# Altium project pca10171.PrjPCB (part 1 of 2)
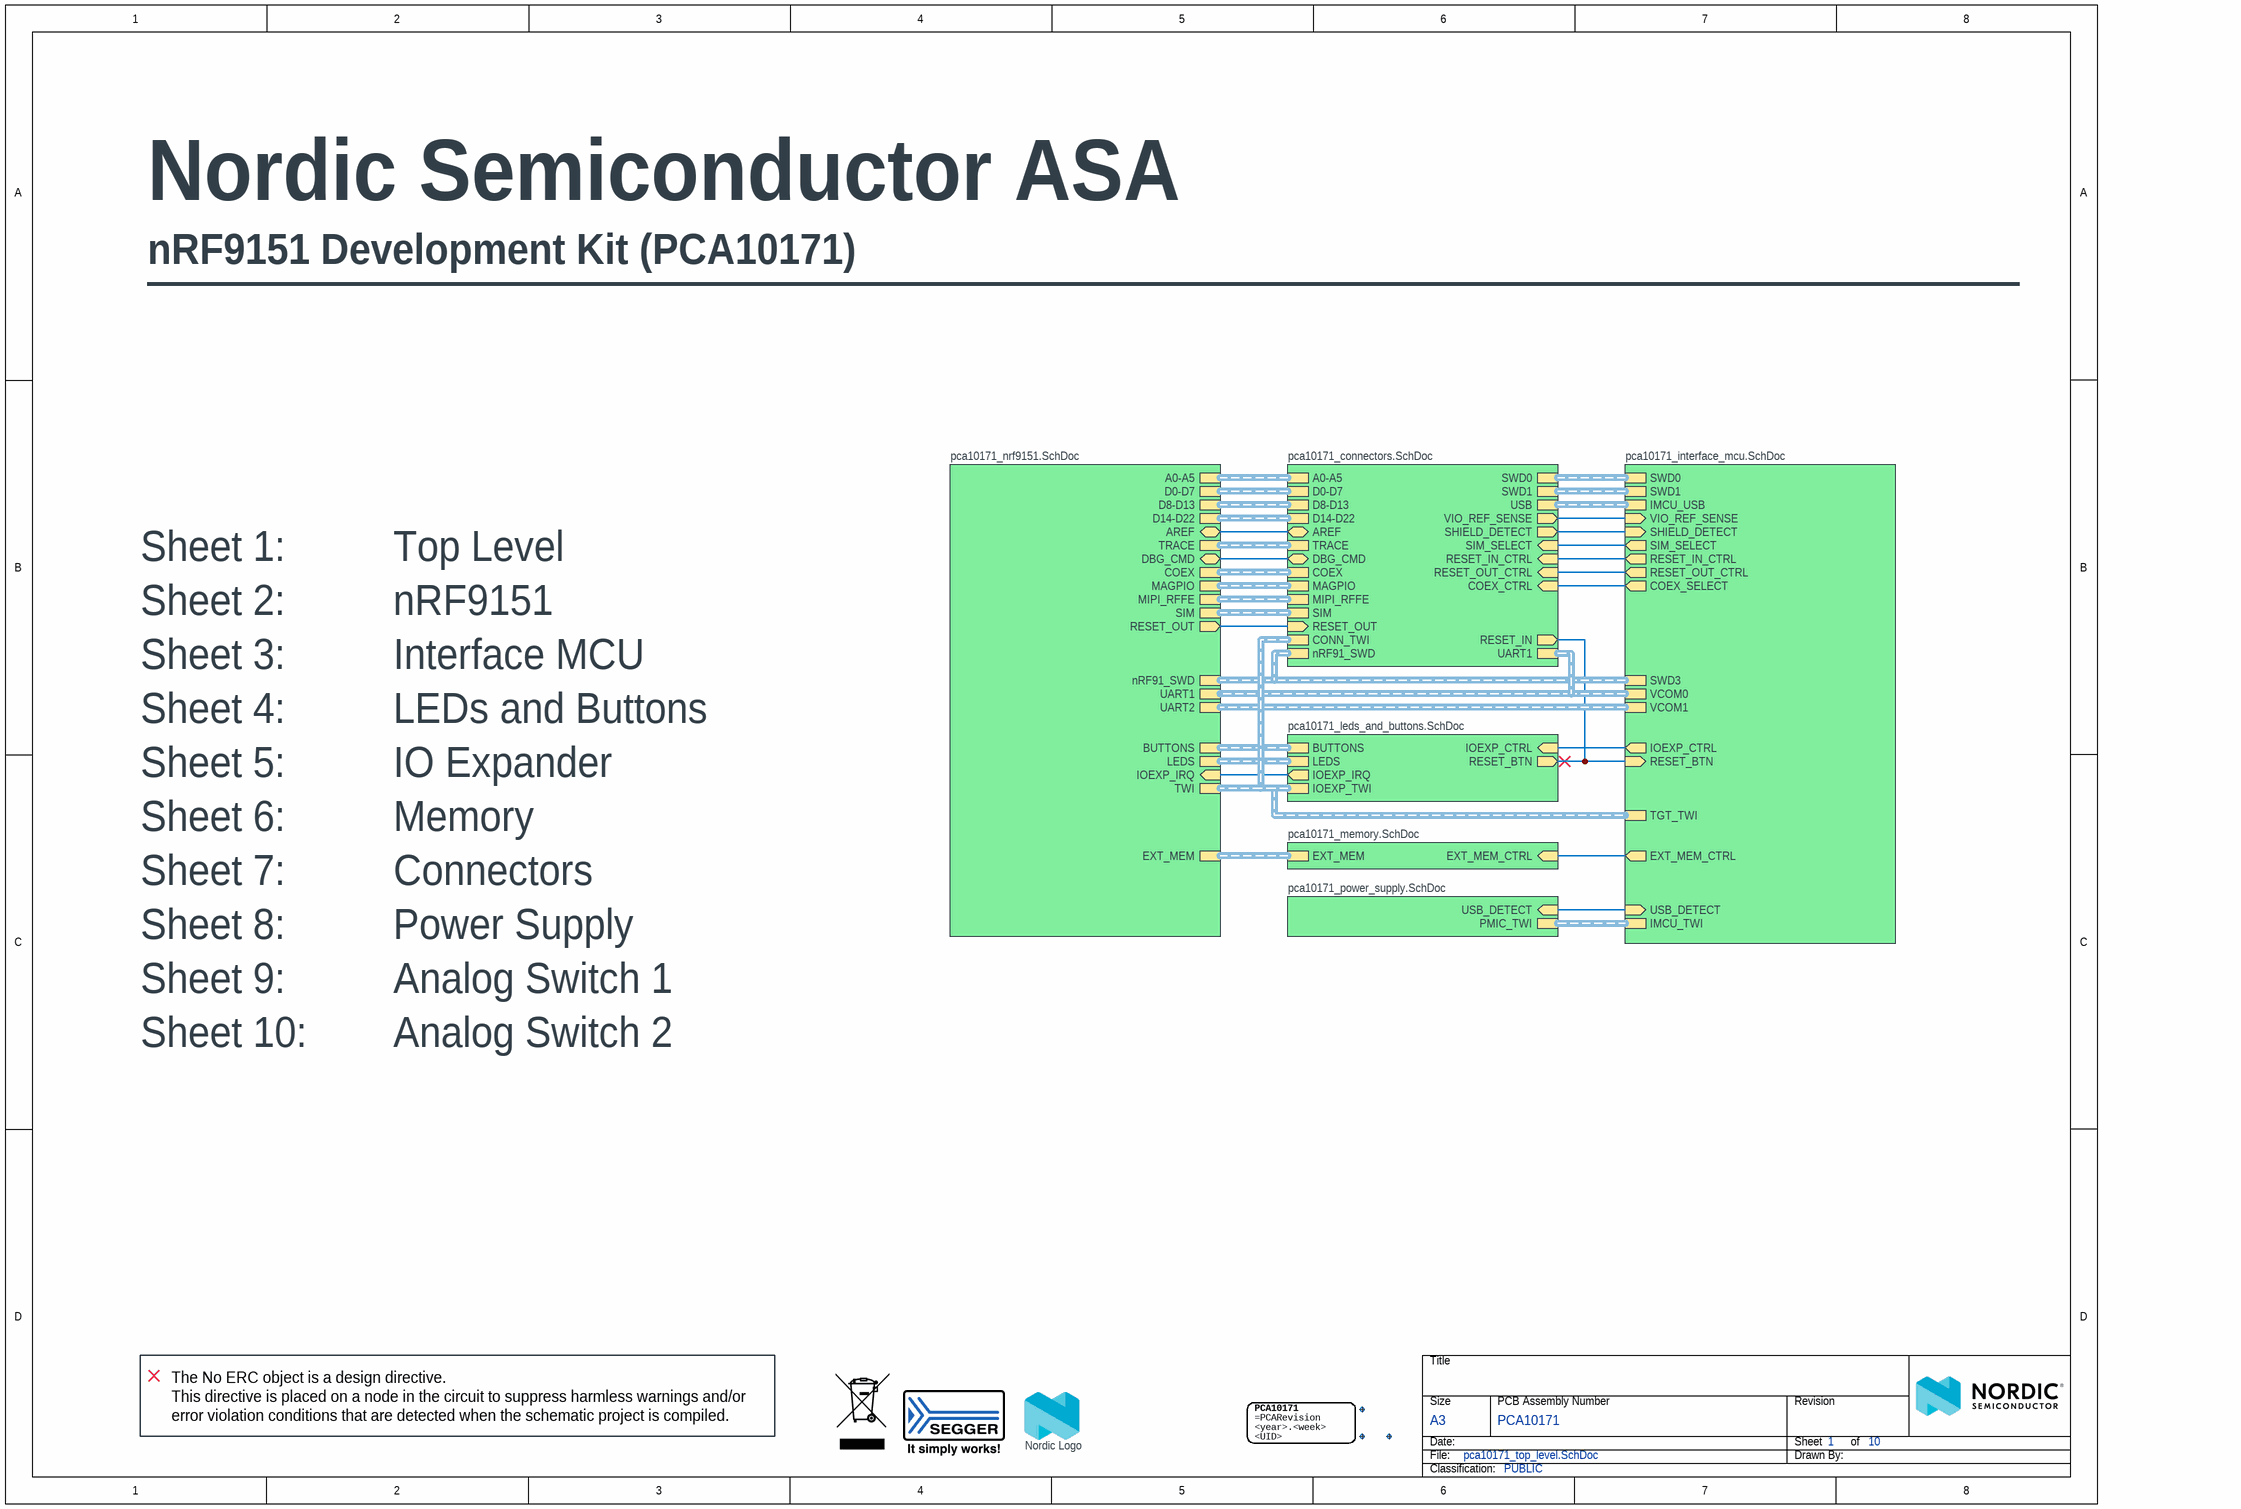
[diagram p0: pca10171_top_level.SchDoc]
BoardThickness: 1.6mm; BoardTitle: nRF9151 Development Kit; Classification: PUBLIC; Compliance: RoHS, REACH, Halogen-Free; Designer: KOD1; Dielectric: FR-4; NrOfLayers: 4; Organization: Nordic Semiconductor; PCAName: PCA10171; PCARevision: 1.0.0; PCBNumber: 400797; PCBRevision: 0022KOD1; PCBStackup: 4001; ProductName: nRF9151-DK; ProjectName: nRF91 DK; ProjectNumber: 4536; SilkscreenColor: White; SoldermaskColor: Blue; SurfaceFinish: ENIG Gold
10 sheets, 317 parts. Net scope: hierarchical (ports join the sheet entries above them; power ports are global).
Board file: 400797.PcbDoc
Sheets:
  pca10171_top_level.SchDoc
     = pca10171_nrf9151.SchDoc
     = pca10171_interface_mcu.SchDoc
      S1 = pca10171_switch_fsa.SchDoc
      S2 = pca10171_switch_fsa.SchDoc
      S3 = pca10171_switch_fsa.SchDoc
      S4 = pca10171_switch_fsa.SchDoc
     = pca10171_leds_and_buttons.SchDoc
      S5 = pca10171_switch_fsa.SchDoc
      S6 = pca10171_switch_fsa.SchDoc
      S7 = pca10171_switch_nx.SchDoc
      Designator = pca10171_io_expander.SchDoc
     = pca10171_memory.SchDoc
      S8 = pca10171_switch_fsa.SchDoc
     = pca10171_connectors.SchDoc
      S9 = pca10171_switch_nx.SchDoc
      S10 = pca10171_switch_fsa.SchDoc
      S11 = pca10171_switch_fsa.SchDoc
     = pca10171_power_supply.SchDoc

## Sheet pca10171_top_level.SchDoc: =BoardTitle + ' - Top Level'
size A3; Organization: Nordic Semiconductor; DocumentNumber: 1; Revision: 1.0.0; SheetNumber: 1; SheetTotal: 10; Author: KOD1; CompanyName: Nordic Semiconductor; DrawnBy: KOD1; DocumentSize: A3

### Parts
Fid1  Fiducial mark  [Fiducial]  (value not drawn)  (no BOM)
Fid2  Fiducial mark  [Fiducial]  (value not drawn)  (no BOM)
Fid3  Fiducial mark  [Fiducial]  (value not drawn)  (no BOM)
LABEL1  15x40mm  [LabelSilk_15x40]  (value not drawn)
LOGO1  WEE Symbol  [WEE_3x4.5mm]  (value not drawn)  (no BOM)
LOGO2  Segger Logo S  [SEGGER_LOGO_S]  (value not drawn)  (no BOM)
LOGO3  Nordic Logo  [NORDIC_LOGO_LYING]  (no BOM)

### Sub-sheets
? = pca10171_nrf9151.SchDoc: nRF91_SWD (harness SWD), DBG_CMD (bidir), UART1 (harness UART), COEX (harness COEX), UART2 (harness UART), SIM (harness SIM), TWI (harness TWI), A0-A5 (harness 6CH), AREF (bidir), TRACE (harness TRACE), BUTTONS (harness 4CH), LEDS (harness 4CH), IOEXP_IRQ (in), EXT_MEM (harness SPI), MIPI_RFFE (harness MIPI_RFFE), MAGPIO (harness MAGPIO), RESET_OUT (out), D8-D13 (harness 6CH), D14-D22 (harness 9CH), D0-D7 (harness 8CH)
? = pca10171_interface_mcu.SchDoc: VCOM1 (harness UART), VCOM0 (harness UART), USB_DETECT (in), RESET_BTN (in), SWD3 (harness SWD), SWD1 (harness SWD), IMCU_USB (harness USB), SWD0 (harness SWD), COEX_SELECT (out), IOEXP_CTRL (out), SIM_SELECT (out), TGT_TWI (harness TWI), VIO_REF_SENSE (in), IMCU_TWI (harness TWI), RESET_IN_CTRL (out), EXT_MEM_CTRL (out), SHIELD_DETECT (in), RESET_OUT_CTRL (out)
? = pca10171_leds_and_buttons.SchDoc: BUTTONS (harness 4CH), LEDS (harness 4CH), IOEXP_CTRL (in), IOEXP_IRQ (out), RESET_BTN (out), IOEXP_TWI (harness TWI)
? = pca10171_memory.SchDoc: EXT_MEM_CTRL (in), EXT_MEM (harness SPI)
? = pca10171_connectors.SchDoc: COEX (harness COEX), nRF91_SWD (harness SWD), DBG_CMD (bidir), MIPI_RFFE (harness MIPI_RFFE), A0-A5 (harness 6CH), TRACE (harness TRACE), USB (harness USB), SIM (harness SIM), AREF (bidir), MAGPIO (harness MAGPIO), SWD0 (harness SWD), SWD1 (harness SWD), SHIELD_DETECT (out), UART1 (harness UART), SIM_SELECT (in), VIO_REF_SENSE (out), CONN_TWI (harness TWI), RESET_IN_CTRL (in), RESET_OUT (in), RESET_OUT_CTRL (in), RESET_IN (out), D8-D13 (harness 6CH), D14-D22 (harness 9CH), D0-D7 (harness 8CH), COEX_CTRL (in)
? = pca10171_power_supply.SchDoc: USB_DETECT (in), PMIC_TWI (harness TWI)

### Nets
COEX_SELECT: sheet /COEX_SELECT, sheet /COEX_CTRL
DBG_CMD: sheet /DBG_CMD, sheet /DBG_CMD
EXT_MEM_CTRL: sheet /EXT_MEM_CTRL, sheet /EXT_MEM_CTRL
IOEXP_CTRL: sheet /IOEXP_CTRL, sheet /IOEXP_CTRL
P0.19/AIN6: sheet /IOEXP_IRQ, sheet /IOEXP_IRQ
P0.20/AIN7: sheet /AREF, sheet /AREF
P0.21: sheet /RESET_OUT, sheet /RESET_OUT
RESET_BUTTON: sheet /RESET_BTN, sheet /RESET_BTN, sheet /RESET_IN
RESET_IN_CTRL: sheet /RESET_IN_CTRL, sheet /RESET_IN_CTRL
RESET_OUT_CTRL: sheet /RESET_OUT_CTRL, sheet /RESET_OUT_CTRL
SHIELD_DETECT: sheet /SHIELD_DETECT, sheet /SHIELD_DETECT
SIM_SELECT: sheet /SIM_SELECT, sheet /SIM_SELECT
USB_DETECT: sheet /USB_DETECT, sheet /USB_DETECT
VIO_REF_SENSE: sheet /VIO_REF_SENSE, sheet /VIO_REF_SENSE

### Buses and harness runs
harness sheet /CONN_TWI = sheet /IOEXP_TWI = sheet /TGT_TWI = sheet /TWI
harness sheet /IMCU_TWI = sheet /PMIC_TWI
harness sheet /IMCU_USB = sheet /USB
harness sheet /nRF91_SWD = sheet /SWD3
harness sheet /UART1 = sheet /VCOM0
harness sheet /UART2 = sheet /VCOM1

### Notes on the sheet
- Nordic Semiconductor ASA
- ________________________________________________________________
- Sheet 1:          Top Level
- Sheet 2:          nRF9151
- Sheet 3:          Interface MCU
- Sheet 4:          LEDs and Buttons
- Sheet 5:          IO Expander
- Sheet 6:          Memory
- Sheet 7:          Connectors
- Sheet 8:          Power Supply
- Sheet 9:          Analog Switch 1
- Sheet 10:        Analog Switch 2
- The No ERC object is a design directive.
  This directive is placed on a node in the circuit to suppress harmless warnings and/or error violation conditions that are detected when the schematic project is compiled.

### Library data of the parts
Fid1-Fid3 = Fid-Mark: Manufacturer: N.A.; Part number NEMS: 100500073; Value: N.A.; Assembly: Not mounted; Pad Count: 1; Component Status: Active; System: Connector
LABEL1 = Label_15x40: PCA version label, stick-on, 15x40mm; Manufacturer: Ellco Etikett; Manufacturer Part Number: 51945; Part number NEMS: 101200030; Component Status: Active; Pad Count: 0; Note: N.A.; Assembly: See section for "Marking/ Stick-on label specification
LOGO1 = WEEE Symbol 3x4.5mm: WEEE Directive symbol; Manufacturer: N.A.; Part number NEMS: 101100006; Component Status: Active; Pad Count: 0
LOGO2 = Segger Logo S: Segger logo, small size; Manufacturer: N.A.; Part number NEMS: 101100004; Component Status: Active; Pad Count: 0
LOGO3 = Nordic Logo lying: Manufacturer: N.A.; Part number NEMS: 101100001; Component Status: Active; Pad Count: 0

## Sheet pca10171_nrf9151.SchDoc: =BoardTitle + ' - nRF9151'
size A3; Organization: Nordic Semiconductor; DocumentNumber: 2; Revision: 1.0.0; SheetNumber: 2; SheetTotal: 10; Author: KOD1; CompanyName: Nordic Semiconductor; DrawnBy: KOD1; DocumentSize: A3
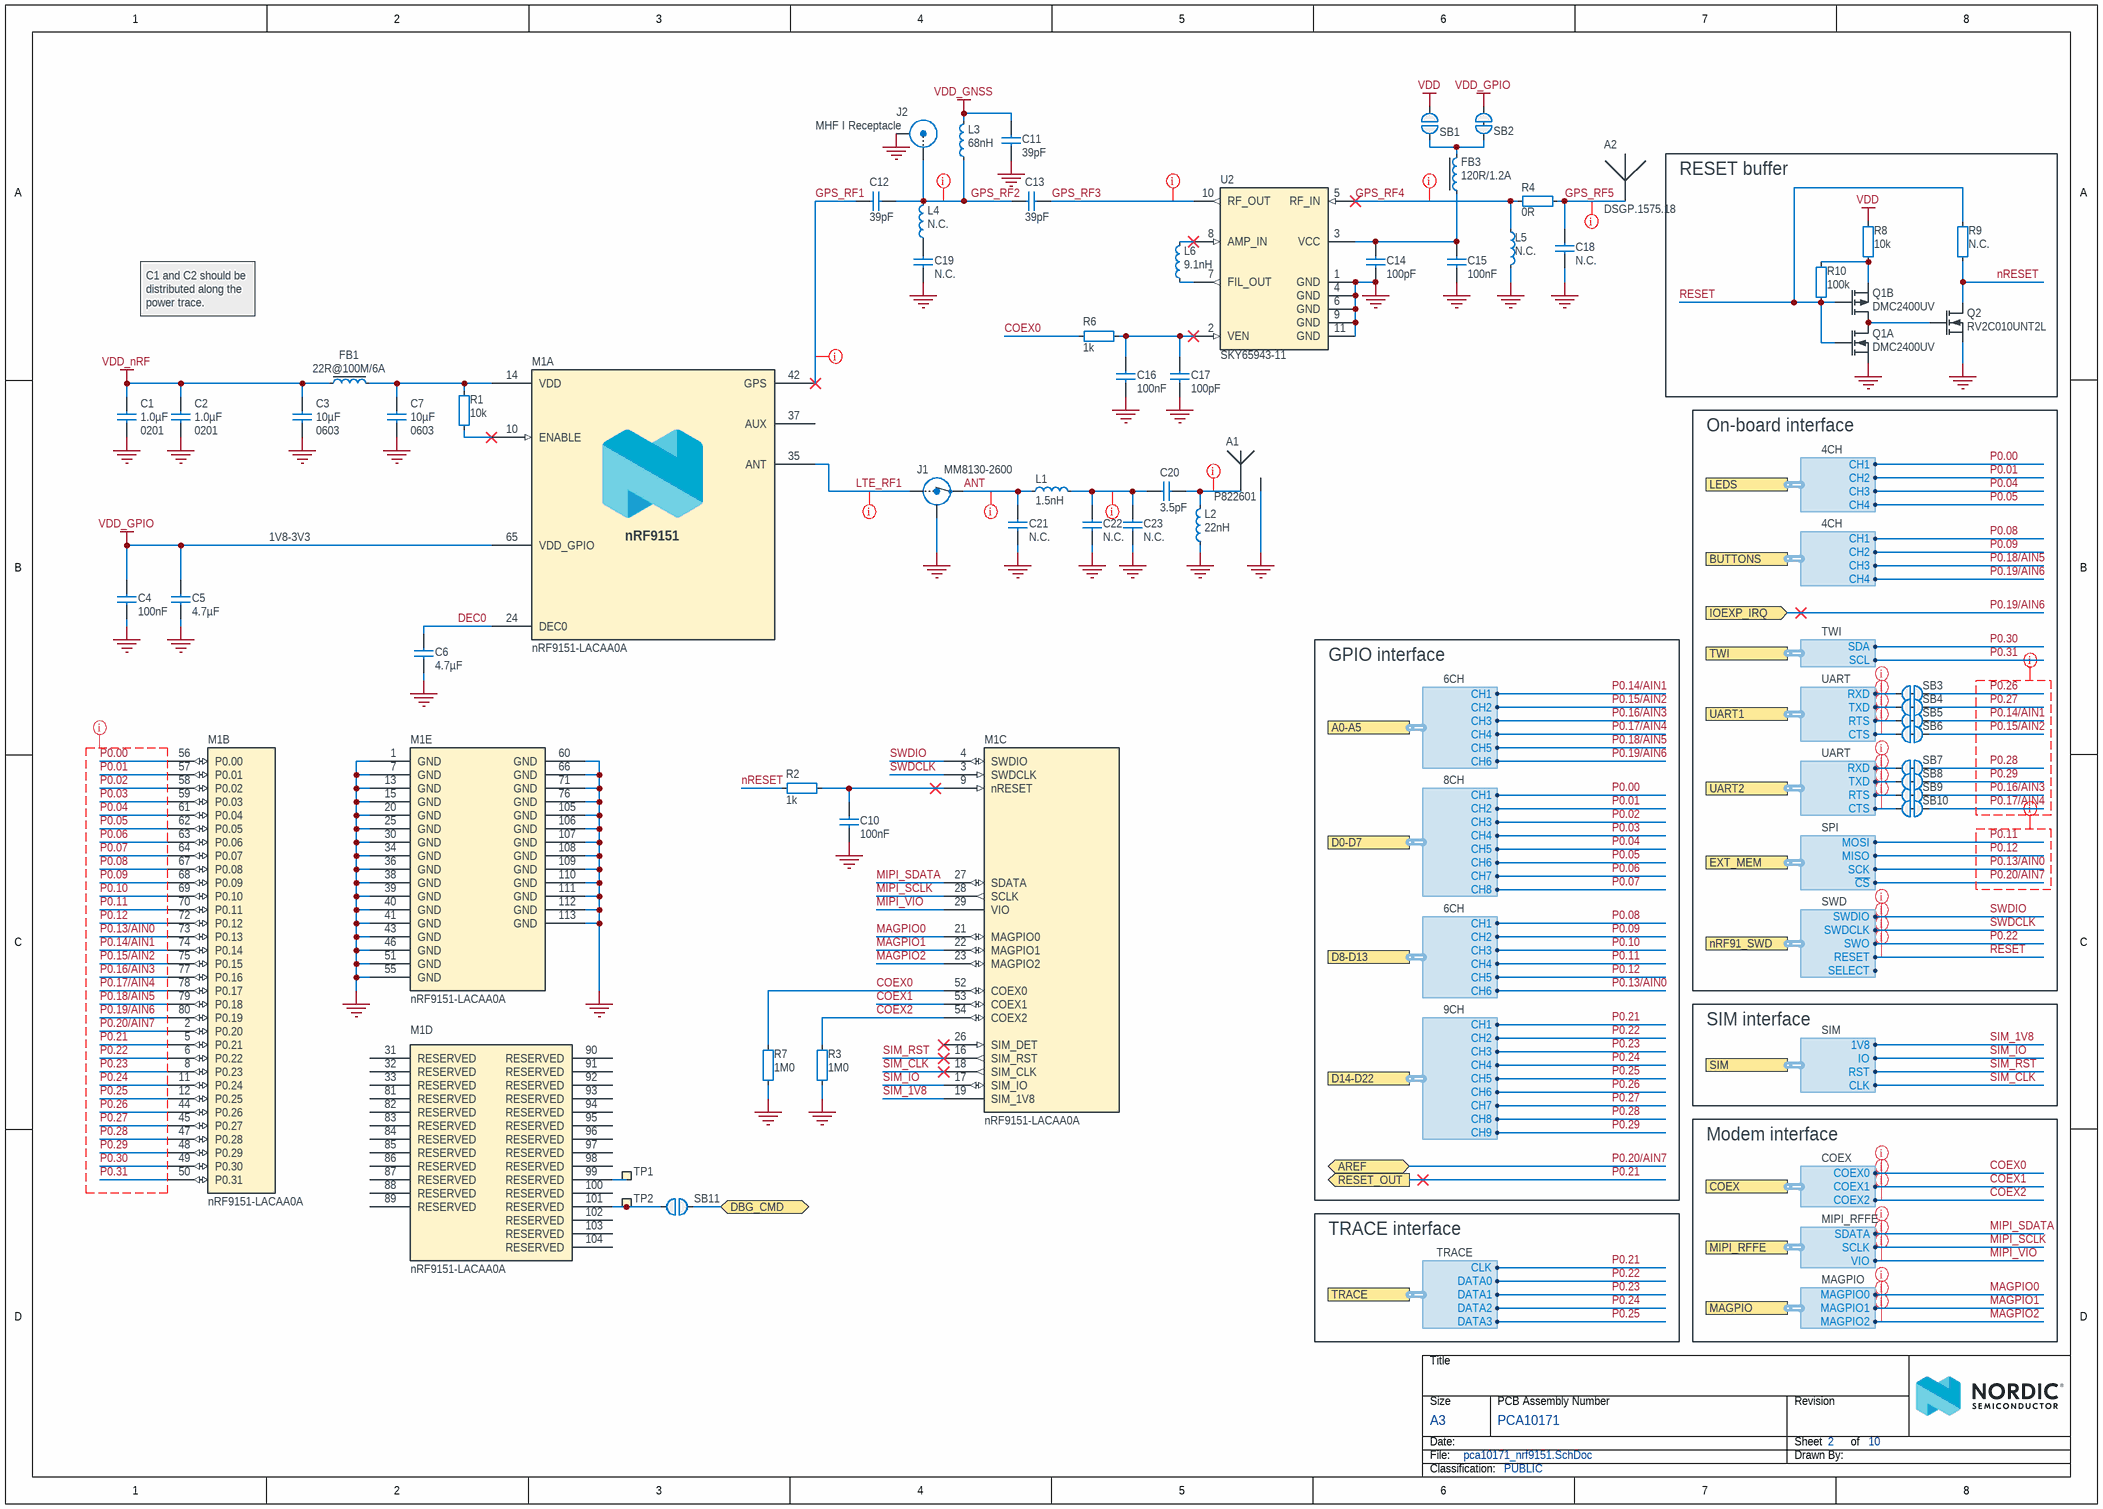
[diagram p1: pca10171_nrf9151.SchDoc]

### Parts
A1  P822601  [P822601]
A2  DSGP.1575.18  [DSGP.1575.18.4.C.02]
C1  1.0µF  Footprint Doc: 0201  [CAPC0603X03L_C]
C2  1.0µF  Footprint Doc: 0201  [CAPC0603X03L_C]
C3  10µF  Footprint Doc: 0603  [CAPC1608X06L]
C4  100nF  [CAPC0603X03L_C]
C5  4.7µF  [CAPC1005X04L]
C6  4.7µF  [CAPC1005X04L]
C7  10µF  Footprint Doc: 0603  [CAPC1608X06L]
C10  100nF  [CAPC0603X03L_C]
C11  39pF  [CAPC0603X03L_C]
C12  39pF  [CAPC0603X03L_C]
C13  39pF  [CAPC0603X03L_C]
C14  100pF  [CAPC0603X03L_C]
C15  100nF  [CAPC0603X03L_C]
C16  100nF  [CAPC0603X03L_C]
C17  100pF  [CAPC0603X03L_C]
C18  N.C.  [CAPC1005X04L_NC]
C19  N.C.  [CAPC0603X03L_C_NC]
C20  3.5pF  [CAPC0603X03L_C]
C21  N.C.  [CAPC0603X03L_C_NC]
C22  N.C.  [CAPC0603X03L_C_NC]
C23  N.C.  [CAPC0603X03L_C_NC]
FB1  22R@100M/6A  [INDC1608X06L]
FB3  120R/1.2A  [INDC1005X04L]
J1  MM8130-2600  [COAXIAL-SWF]
J2  MHF I Receptacle  [COAXIAL RF U.FL-R-SMT-1]
L1  1.5nH  [INDC0603X03L_C]
L2  22nH  [INDC0603X03L_C]
L3  68nH  [INDC1005X04L_WW]
L4  N.C.  [INDC1005X04L_NC]
L5  N.C.  [INDC1005X04L_NC]
L6  9.1nH  [INDC1005X04L_WW]
M1  nRF9151-LACAA0A  [LGA50P1210X1110X130-113N]  (parts A,B,C,D,E of 5)
Q1  DMC2400UV  [SOTFL50P162X60-6N]  (parts A,B of 2)
Q2  RV2C010UNT2L  [DFN65P100X40-3L]
R1  10k  [RESC0603X03L_C]
R2  1k  [RESC0603X03L_C]
R3  1M0  [RESC0603X03L_C]
R4  0R  [RESC1005X04L]
R6  1k  [RESC0603X03L_C]
R7  1M0  [RESC0603X03L_C]
R8  10k  [RESC0603X03L_C]
R9  N.C.  [RESC0603X03L_C_NC]
R10  100k  [RESC0603X03L_C]
SB1  Solderbridge  [Solderbridge]  (value not drawn)  (no BOM)
SB2  Solderbridge  [Solderbridge_Shorted]  (value not drawn)  (net tie, no BOM)
SB3  Solderbridge  [Solderbridge_Shorted]  (value not drawn)  (net tie, no BOM)
SB4  Solderbridge  [Solderbridge_Shorted]  (value not drawn)  (net tie, no BOM)
SB5  Solderbridge  [Solderbridge_Shorted]  (value not drawn)  (net tie, no BOM)
SB6  Solderbridge  [Solderbridge_Shorted]  (value not drawn)  (net tie, no BOM)
SB7  Solderbridge  [Solderbridge_Shorted]  (value not drawn)  (net tie, no BOM)
SB8  Solderbridge  [Solderbridge_Shorted]  (value not drawn)  (net tie, no BOM)
SB9  Solderbridge  [Solderbridge_Shorted]  (value not drawn)  (net tie, no BOM)
SB10  Solderbridge  [Solderbridge_Shorted]  (value not drawn)  (net tie, no BOM)
SB11  Solderbridge  [Solderbridge]  (value not drawn)  (no BOM)
TP1  Ø1.0mm,SMD  [TP_SMD_D1.0mm]  (value not drawn)  (no BOM)
TP2  Ø1.0mm,SMD  [TP_SMD_D1.0mm]  (value not drawn)  (no BOM)
U2  SKY65943-11  [SKY65943-11]

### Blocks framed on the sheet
RESET buffer: Q1 Q2 R8-R10
On-board interface: SB3-SB10

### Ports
A0-A5 (harness 6CH), AREF (bidir), BUTTONS (harness 4CH), COEX (harness COEX), D0-D7 (harness 8CH), D8-D13 (harness 6CH), D14-D22 (harness 9CH), DBG_CMD (bidir), EXT_MEM (harness SPI), IOEXP_IRQ (in), LEDS (harness 4CH), MAGPIO (harness MAGPIO), MIPI_RFFE (harness MIPI_RFFE), nRF91_SWD (harness SWD), RESET_OUT (out), SIM (harness SIM), TRACE (harness TRACE), TWI (harness TWI), UART1 (harness UART), UART2 (harness UART)

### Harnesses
COEX: COEX0, COEX2, COEX1
UART: RTS, CTS, RXD, TXD
SIM: CLK, IO, 1V8, RST
SWD: SWDIO, SWDCLK, SWO, RESET, SELECT
TWI: SCL, SDA
TRACE: CLK, DATA0, DATA1, DATA3, DATA2
SPI: SCK, ~{CS}, MOSI, MISO
MIPI_RFFE: SDATA, VIO, SCLK
MAGPIO: MAGPIO0, MAGPIO2, MAGPIO1
4CH: CH1, CH2, CH3, CH4
6CH: CH1, CH2, CH3, CH4, CH5, CH6
8CH: CH1, CH2, CH3, CH4, CH5, CH6, CH7, CH8
9CH: CH1, CH2, CH3, CH4, CH5, CH6, CH7, CH8, CH9

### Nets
GND: A1.2 A2.2(GND) C1.2 C2.2 C3.2 C4.2 C5.2 C6.2 C7.2 C10.2 C11.1 C14.1 C15.1 C16.1 C17.1 C18.2 C19.1 C21.1 C22.1 C23.1 J1.2(Shield) J2.2(Y) L2.1 L5.2 M1.1(GND) M1.7(GND) M1.13(GND) M1.15(GND) M1.20(GND) M1.25(GND) M1.30(GND) M1.34(GND) M1.36(GND) M1.38(GND) M1.39(GND) M1.40(GND) M1.41(GND) M1.43(GND) M1.46(GND) M1.51(GND) M1.55(GND) M1.60(GND) M1.66(GND) M1.71(GND) M1.76(GND) M1.105(GND) M1.106(GND) M1.107(GND) M1.108(GND) M1.109(GND) M1.110(GND) M1.111(GND) M1.112(GND) M1.113(GND) Q1.1(S1) Q2.2(S) R3.1 R7.1 U2.1(GND) U2.4(GND) U2.6(GND) U2.9(GND) U2.11(GND)
VDD: R8.1 SB1.1
VDD_GNSS: C11.2 L3.1
VDD_GPIO: C4.1 C5.1 M1.65(VDD_GPIO) SB2.1
VDD_nRF: C1.1 C2.1 C3.1 FB1.1
ANT: C21.2 J1.3(OUT) L1.1
COEX0: M1.52(COEX0) R6.1 R7.2 ; port COEX.COEX0
COEX1: M1.53(COEX1) ; port COEX.COEX1
COEX2: M1.54(COEX2) R3.2 ; port COEX.COEX2
DBG_CMD: SB11.1 ; port DBG_CMD
DEC0: C6.1 M1.24(DEC0)
GPS_RF1: C12.2 M1.42(GPS)
GPS_RF2: C12.1 C13.2 J2.1(X) L3.2 L4.1
GPS_RF3: C13.1 U2.10(RF_OUT)
GPS_RF4: L5.1 R4.1 U2.5(RF_IN)
GPS_RF5: A2.1 C18.1 R4.2
LTE_RF1: J1.1(IN) M1.35(ANT)
MAGPIO0: M1.21(MAGPIO0) ; port MAGPIO.MAGPIO0
MAGPIO1: M1.22(MAGPIO1) ; port MAGPIO.MAGPIO1
MAGPIO2: M1.23(MAGPIO2) ; port MAGPIO.MAGPIO2
MIPI_SCLK: M1.28(SCLK) ; port MIPI_RFFE.SCLK
MIPI_SDATA: M1.27(SDATA) ; port MIPI_RFFE.SDATA
MIPI_VIO: M1.29(VIO) ; port MIPI_RFFE.VIO
nRESET: Q2.3(D) R2.1 R9.2
P0.00: M1.56(P0.00) ; port LEDS.CH1, port D0-D7.CH1
P0.01: M1.57(P0.01) ; port LEDS.CH2, port D0-D7.CH2
P0.02: M1.58(P0.02) ; port D0-D7.CH3
P0.03: M1.59(P0.03) ; port D0-D7.CH4
P0.04: M1.61(P0.04) ; port LEDS.CH3, port D0-D7.CH5
P0.05: M1.62(P0.05) ; port LEDS.CH4, port D0-D7.CH6
P0.06: M1.63(P0.06) ; port D0-D7.CH7
P0.07: M1.64(P0.07) ; port D0-D7.CH8
P0.08: M1.67(P0.08) ; port BUTTONS.CH1, port D8-D13.CH1
P0.09: M1.68(P0.09) ; port BUTTONS.CH2, port D8-D13.CH2
P0.10: M1.69(P0.10) ; port D8-D13.CH3
P0.11: M1.70(P0.11) ; port EXT_MEM.MOSI, port D8-D13.CH4
P0.12: M1.72(P0.12) ; port EXT_MEM.MISO, port D8-D13.CH5
P0.13/AIN0: M1.73(P0.13) ; port EXT_MEM.SCK, port D8-D13.CH6
P0.14/AIN1: M1.74(P0.14) SB5.1 ; port A0-A5.CH1
P0.15/AIN2: M1.75(P0.15) SB6.1 ; port A0-A5.CH2
P0.16/AIN3: M1.77(P0.16) SB9.1 ; port A0-A5.CH3
P0.17/AIN4: M1.78(P0.17) SB10.1 ; port A0-A5.CH4
P0.18/AIN5: M1.79(P0.18) ; port BUTTONS.CH3, port A0-A5.CH5
P0.19/AIN6: M1.80(P0.19) ; port IOEXP_IRQ, port BUTTONS.CH4, port A0-A5.CH6
P0.20/AIN7: M1.2(P0.20) ; port AREF, port EXT_MEM.~{CS}
P0.21: M1.5(P0.21) ; port RESET_OUT, port TRACE.CLK, port D14-D22.CH1
P0.22: M1.6(P0.22) ; port nRF91_SWD.SWO, port TRACE.DATA0, port D14-D22.CH2
P0.23: M1.8(P0.23) ; port TRACE.DATA1, port D14-D22.CH3
P0.24: M1.11(P0.24) ; port TRACE.DATA2, port D14-D22.CH4
P0.25: M1.12(P0.25) ; port TRACE.DATA3, port D14-D22.CH5
P0.26: M1.44(P0.26) SB3.1 ; port D14-D22.CH6
P0.27: M1.45(P0.27) SB4.1 ; port D14-D22.CH7
P0.28: M1.47(P0.28) SB7.1 ; port D14-D22.CH8
P0.29: M1.48(P0.29) SB8.1 ; port D14-D22.CH9
P0.30: M1.49(P0.30) ; port TWI.SDA
P0.31: M1.50(P0.31) ; port TWI.SCL
RESET: Q1.2(G1) Q1.5(G2) R9.1 R10.1 ; port nRF91_SWD.RESET
SIM_1V8: M1.19(SIM_1V8) ; port SIM.1V8
SIM_CLK: M1.18(SIM_CLK) ; port SIM.CLK
SIM_IO: M1.17(SIM_IO) ; port SIM.IO
SIM_RST: M1.16(SIM_RST) ; port SIM.RST
SWDCLK: M1.3(SWDCLK) ; port nRF91_SWD.SWDCLK
SWDIO: M1.4(SWDIO) ; port nRF91_SWD.SWDIO
NetA1_1: A1.1 C20.2 L2.2
NetC7_1: C7.1 FB1.2 M1.14(VDD) R1.1
NetC10_1: C10.1 M1.9(nRESET) R2.2
NetC14_2: C14.2 C15.2 FB3.1 U2.3(VCC)
NetC16_2: C16.2 C17.2 R6.2 U2.2(VEN)
NetC19_2: C19.2 L4.2
NetC20_1: C20.1 C22.2 C23.2 L1.2
NetFB3_2: FB3.2 SB1.2 SB2.2
NetL6_1: L6.1 U2.8(AMP_IN)
NetL6_2: L6.2 U2.7(FIL_OUT)
NetM1_10: M1.10(ENABLE) R1.2
NetM1_99: M1.99(RESERVED) TP1.1
NetM1_101: M1.101(RESERVED) SB11.2 TP2.1
NetP29_2: SB5.2 ; port UART1.RTS
NetP29_4: SB3.2 ; port UART1.RXD
NetP29_5: SB4.2 ; port UART1.TXD
NetP29_6: SB6.2 ; port UART1.CTS
NetQ1_3: Q1.3(D2) Q1.6(D1) Q2.1(G)
NetQ1_4: Q1.4(S2) R8.2 R10.2
NetSB7_2: SB7.2 ; port UART2.RXD
NetSB8_2: SB8.2 ; port UART2.TXD
NetSB9_2: SB9.2 ; port UART2.RTS
NetSB10_2: SB10.2 ; port UART2.CTS

Not connected (* = marked no-connect by the designer): M1 26(SIM_DET)* 31(RESERVED) 32(RESERVED) 33(RESERVED) 37(AUX) 81(RESERVED) 82(RESERVED) 83(RESERVED) 84(RESERVED) 85(RESERVED) 86(RESERVED) 87(RESERVED) 88(RESERVED) 89(RESERVED) 90(RESERVED) 91(RESERVED) 92(RESERVED) 93(RESERVED) 94(RESERVED) 95(RESERVED) 96(RESERVED) 97(RESERVED) 98(RESERVED) 100(RESERVED) 102(RESERVED) 103(RESERVED) 104(RESERVED)

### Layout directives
net class SWD: P0.22, RESET, SWDCLK, SWDIO
net class COEX: COEX0, COEX1, COEX2, MAGPIO0, MAGPIO1, MAGPIO2, MIPI_SCLK, MIPI_SDATA, MIPI_VIO
net class GPIO: NetP29_2, NetP29_4, NetP29_5, NetP29_6, NetSB7_2, NetSB8_2, NetSB9_2, NetSB10_2, P0.00, P0.01, P0.02, P0.03, P0.04, P0.05, P0.06, P0.07, P0.08, P0.09, P0.10, P0.11, P0.12, P0.13/AIN0, P0.14/AIN1, P0.15/AIN2, P0.16/AIN3, P0.17/AIN4, P0.18/AIN5, P0.19/AIN6, P0.20/AIN7, P0.21, P0.22, P0.23, P0.24, P0.25, P0.26, P0.27, P0.28, P0.29, P0.30, P0.31
net class RF: ANT, GPS_RF1, GPS_RF2, GPS_RF3, GPS_RF4, GPS_RF5, LTE_RF1, NetA1_1, NetC20_1
net class nRF9151_UART: P0.14/AIN1, P0.15/AIN2, P0.16/AIN3, P0.17/AIN4, P0.26, P0.27, P0.28, P0.29
net class EXT_MEM: P0.11, P0.12, P0.13/AIN0, P0.20/AIN7

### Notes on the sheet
- C1 and C2 should be distributed along the power trace.
- 1V8-3V3
- GPIO interface
- SIM interface
- Modem interface
- TRACE interface

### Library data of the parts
A1 = P822601: ANTENNA PRESTTA OCTABAND LTE; Manufacturer: Ethertronics; Part number IPS: 00000009001; Part number NEMS: 100700043; Note: N.A.; Pad Count: 2; Component Status: Active
A2 = DSGP.1575.18.4.C.02: 18 x 18 mm Low Profile GPS L1 / GALILEO E1 Passive Patch Antenna; Manufacturer: Taoglas; Part number IPS: 00000007687; Part number NEMS: 100700073; Note: N.A.; Pad Count: 2; Component Status: Active
C1 C2 = C0201-1µ0-10V-X5R-GRM033R61A105ME15: Capacitor, X5R, ±20%, 10V; Manufacturer: Murata; Part number NEMS: 100200545; Artikkelnr Noca: N.A.; Pad Count: 2; Component Status: Active
C3 C7 = C0603-10µ-10V-X6S-GRM188C81A106MA73: Capacitor, Ceramic, 10µF 10V X6S 0603,±20%; Manufacturer: Murata; Part number NEMS: 100200520; Component Status: Active; Pad Count: 2; Artikkelnr Noca: N.A.
C4 C10 C15 = C0201-100n: Capacitor, X5R, ±10%; Manufacturer: N.A.; Part number IPS: 00000001248, 00000002505; Part number Norautron: 262071862; Part number NEMS: 100200078; Note: 16V; Pad Count: 2; Component Status: Active
C5 C6 = C0402-4µ7-10V-X5R: Capacitor, X5R, 10V; Manufacturer: Murata; Manufacturer Part Number: GRM155R61A475MEAAD; Part number NEMS: 100200415; Artikkelnr Noca: N.A.; Pad Count: 2; Component Status: Active
C11-C13 = C0201-39p: Capacitor, NP0, ±1%, 25V; Manufacturer: Murata; Manufacturer Part Number: GRM0335C1E390FA01; Part number IPS: 00000001668; Part number NEMS: 100200039; Artikkelnr Noca: N.A.; Pad Count: 2; Component Status: Active
C14 C17 = C0201-100p: Capacitor, NP0, ±2%, 25V; Manufacturer: Murata; Manufacturer Part Number: GRM0335C1E101GA01; Part number IPS: 00000007853; Part number NEMS: 100200044; Artikkelnr Noca: N.A.; Pad Count: 2; Component Status: Active
C16 = C0201-100n: Capacitor, X5R, ±10%; Manufacturer: N.A.; Part number IPS: 00000001248, 00000002505; Part number Norautron: 262071862; Part number NEMS: 100200078; Assembly: Not mounted; Note: 16V; Pad Count: 2; Component Status: Active
C18 = C0402-N.C.: Not mounted; Manufacturer: N.A.; Part number NEMS: 100200105; Assembly: Not mounted; Note: Chip Cap; Pad Count: 2; Component Status: Active
C19 = C0201-N.C.: Not mounted; Manufacturer: N.A.; Part number NEMS: 100200001; Assembly: Not mounted; Note: Chip Cap; Pad Count: 2; Component Status: Active
C20 = C0201-3.5p: Capacitor, NP0, ±0.1pF, 25V; Manufacturer: Murata; Manufacturer Part Number: GJM0335C1H3R5BB01E; Part number IPS: 00000001469; Part number NEMS: 100200023; Artikkelnr Noca: N.A.; Pad Count: 2; Component Status: Active
C21-C23 = C0201-N.C.: Not mounted; Manufacturer: N.A.; Part number NEMS: 100200001; Note: Chip Cap; Assembly: Not mounted; Pad Count: 2; Component Status: Active
FB1 = FB0603-22R@100MHz-6000mA: Ferrite Bead, 22 Ohm @ 100MHz, 6000mA, 8 mOhm Max; Manufacturer: Murata; Manufacturer Part Number: BLM18SD220SN1D; Component Status: Active; Pad Count: 2; Note: Chip EMIFIL Inductor Type Chip Ferrite Bead; Artikkelnr Noca: N.A.
FB3 = FB0402-120R@100M-1200mA: Ferrite Bead, 120 Ohm @ 100MHz, 1200mA, 75 mOhm Max; Manufacturer: Murata; Manufacturer Part Number: BLM15EX121SN1; Part number NEMS: 100300416; Component Status: Active; Pad Count: 2; Note: N.A.
J1 = MM8130-2600: Coaxial Connector with Switch; Manufacturer: Murata; Part number IPS: 00000009955; Part number Norautron: 26030338; Part number NEMS: 100500400; Note: N.A.; Artikkelnr Noca: 55029011; Pad Count: 3; Component Status: Active
J2 = 20279-001E-03: Ultraminiature Coaxial Connector, 50 Ohm, SMD; Manufacturer: Wellshow; Part number IPS: 00000004436; Part number NEMS: 100500636; Note: N.A.; Pad Count: 3; Component Status: Active
L1 = L0201-1n5-HQ-Murata: Inductor, 1000mA, ±0.1ｎH, 50mOhm; Manufacturer: Murata; Manufacturer Part Number: LQP03HQ1N5B02; Part number NEMS: 100300202; Note: -55°C ~ 125°C; Artikkelnr Noca: N.A.; Pad Count: 2; Component Status: Active
L2 = L0201-22n: Chip Inductor; Manufacturer: N.A.; Part number IPS: 00000001478; Part number NEMS: 100300034; Note: High frequency chip inductor ±10%; Pad Count: 2; Component Status: Active
L3 = L0402-68n-Wirewound-Murata: Inductor, 140mA, ±2%, 1960mΩ, Q=20; Manufacturer: Murata; Manufacturer Part Number: LQW15AN68NG00; Part number IPS: 00000002494; Part number NEMS: 100300389; Note: -55°C ~ 125°C; Artikkelnr Noca: N.A.; Pad Count: 2; Component Status: Active
L4 L5 = L0402-N.C.: Not mounted; Manufacturer: N.A.; Part number NEMS: 100300037; Assembly: Not mounted; Pad Count: 2; Component Status: Active
L6 = L0402-9n1-Wirewound-Murata: Inductor, 540mA, ±2%, 140mΩ, Q=25; Manufacturer: Murata; Manufacturer Part Number: LQW15AN9N1G00; Part number IPS: 00000002497; Part number NEMS: 100300357; Note: -55°C ~ 125°C; Artikkelnr Noca: N.A.; Pad Count: 2; Component Status: Active
M1 = nRF9151-LACAA0A: Low power System-in-Package with integrated LTE-M/NB-IoT modem and GPS; Manufacturer: Nordic Semiconductor; Component Status: Active; Pad Count: 113; Note: N.A.
Q1 = DMC2400UV: Dual N & P Ch MOFET, 1.03A/0.7A, 480mOhm, 450mW; Manufacturer: Diodes Incorporated; Part number IPS: 00000007803; Part number NEMS: 101300117; Note: Dual N & P Channel Digital FET; Artikkelnr Noca: N.A.; Pad Count: 6; Component Status: Active
Q2 = RV2C010UNT2L: N-Channel MOSFET, 20V, 1A, 470mOhm, 400mW; Manufacturer: Rohm Semiconductor; Part number IPS: 00000009976; Part number Norautron: 26320026; Part number NEMS: 101300132; Note: N.A.; Artikkelnr Noca: 35010020; Pad Count: 3; Component Status: Active
R1 R8 = R0201-10k: Resistor, ±1%, 0.05W; Manufacturer: N.A.; Part number IPS: 00000001255; Part number Norautron: 26107101; Part number NEMS: 100100065; Note: Chip Res 1%; Pad Count: 2; Component Status: Active
R2 R6 = R0201-1k0: Resistor, ±1%, 0.05W; Manufacturer: N.A.; Part number IPS: 00000005786; Part number NEMS: 100100043; Note: Chip Res 1%; Pad Count: 2; Component Status: Active
R3 R7 = R0201-1M0: Resistor, ±1%, 0.05W; Manufacturer: N.A.; Part number IPS: 00000001418; Part number Norautron: 26107108; Part number NEMS: 100100093; Note: Chip Res 1%; Pad Count: 2; Component Status: Active
R4 = R0402-0R: Resistor, ±5%, 0.063W; Manufacturer: N.A.; Part number IPS: 00000007128; Part number NEMS: 100100109; Note: Chip Res 5%; Artikkelnr Noca: 27049000; Pad Count: 2; Component Status: Active
R9 = R0201-N.C.: Not mounted; Manufacturer: N.A.; Part number NEMS: 100100107; Note: Chip Res; Assembly: Not mounted; Pad Count: 2; Component Status: Active
R10 = R0201-100k: Resistor, ±1%, 0.05W; Manufacturer: N.A.; Part number IPS: 00000001419; Part number Norautron: 26108487; Part number NEMS: 100100080; Note: Chip Res 1%; Pad Count: 2; Component Status: Active
SB1 = Solderbridge: Manufacturer: N.A.; Part number NEMS: 100500458; Component Status: Active; Pad Count: 2; System: Connector
SB2 = Solderbridge Shorted: Shorted Solderbridge; Manufacturer: N.A.; Part number NEMS: 100500459; Component Status: Active; Pad Count: 2; System: Connector
SB3-SB10 = Solderbridge Shorted: Shorted Solderbridge; Manufacturer: N.A.; Part number NEMS: 100500459; Pad Count: 2; Component Status: Active; System: Connector
SB11 = Solderbridge: Manufacturer: N.A.; Part number NEMS: 100500458; Pad Count: 2; Component Status: Active; System: Connector
TP1 TP2 = TP_SMD_Ø1.0MM: 1.0mm circular SMD testpad; Manufacturer: Nordic Semiconductor; Manufacturer Part Number: N.A.; Part number NEMS: 100500475; Pad Count: 1; Component Status: Active
U2 = SKY65943-11: GNSS Low-Noise Amplifier Front-End Module with Integrated Pre-Filter and Post-Filter; Manufacturer: Skyworks; Part number IPS: 00000002997; Part number NEMS: 101900584; Note: N.A.; Pad Count: 10; Component Status: Active

## Sheet pca10171_interface_mcu.SchDoc: =BoardTitle + ' - Interface MCU'
size A3; Organization: Nordic Semiconductor; DocumentNumber: 3; Revision: 1.0.0; SheetNumber: 3; SheetTotal: 10; Author: KOD1; CompanyName: Nordic Semiconductor; DrawnBy: KOD1; DocumentSize: A3
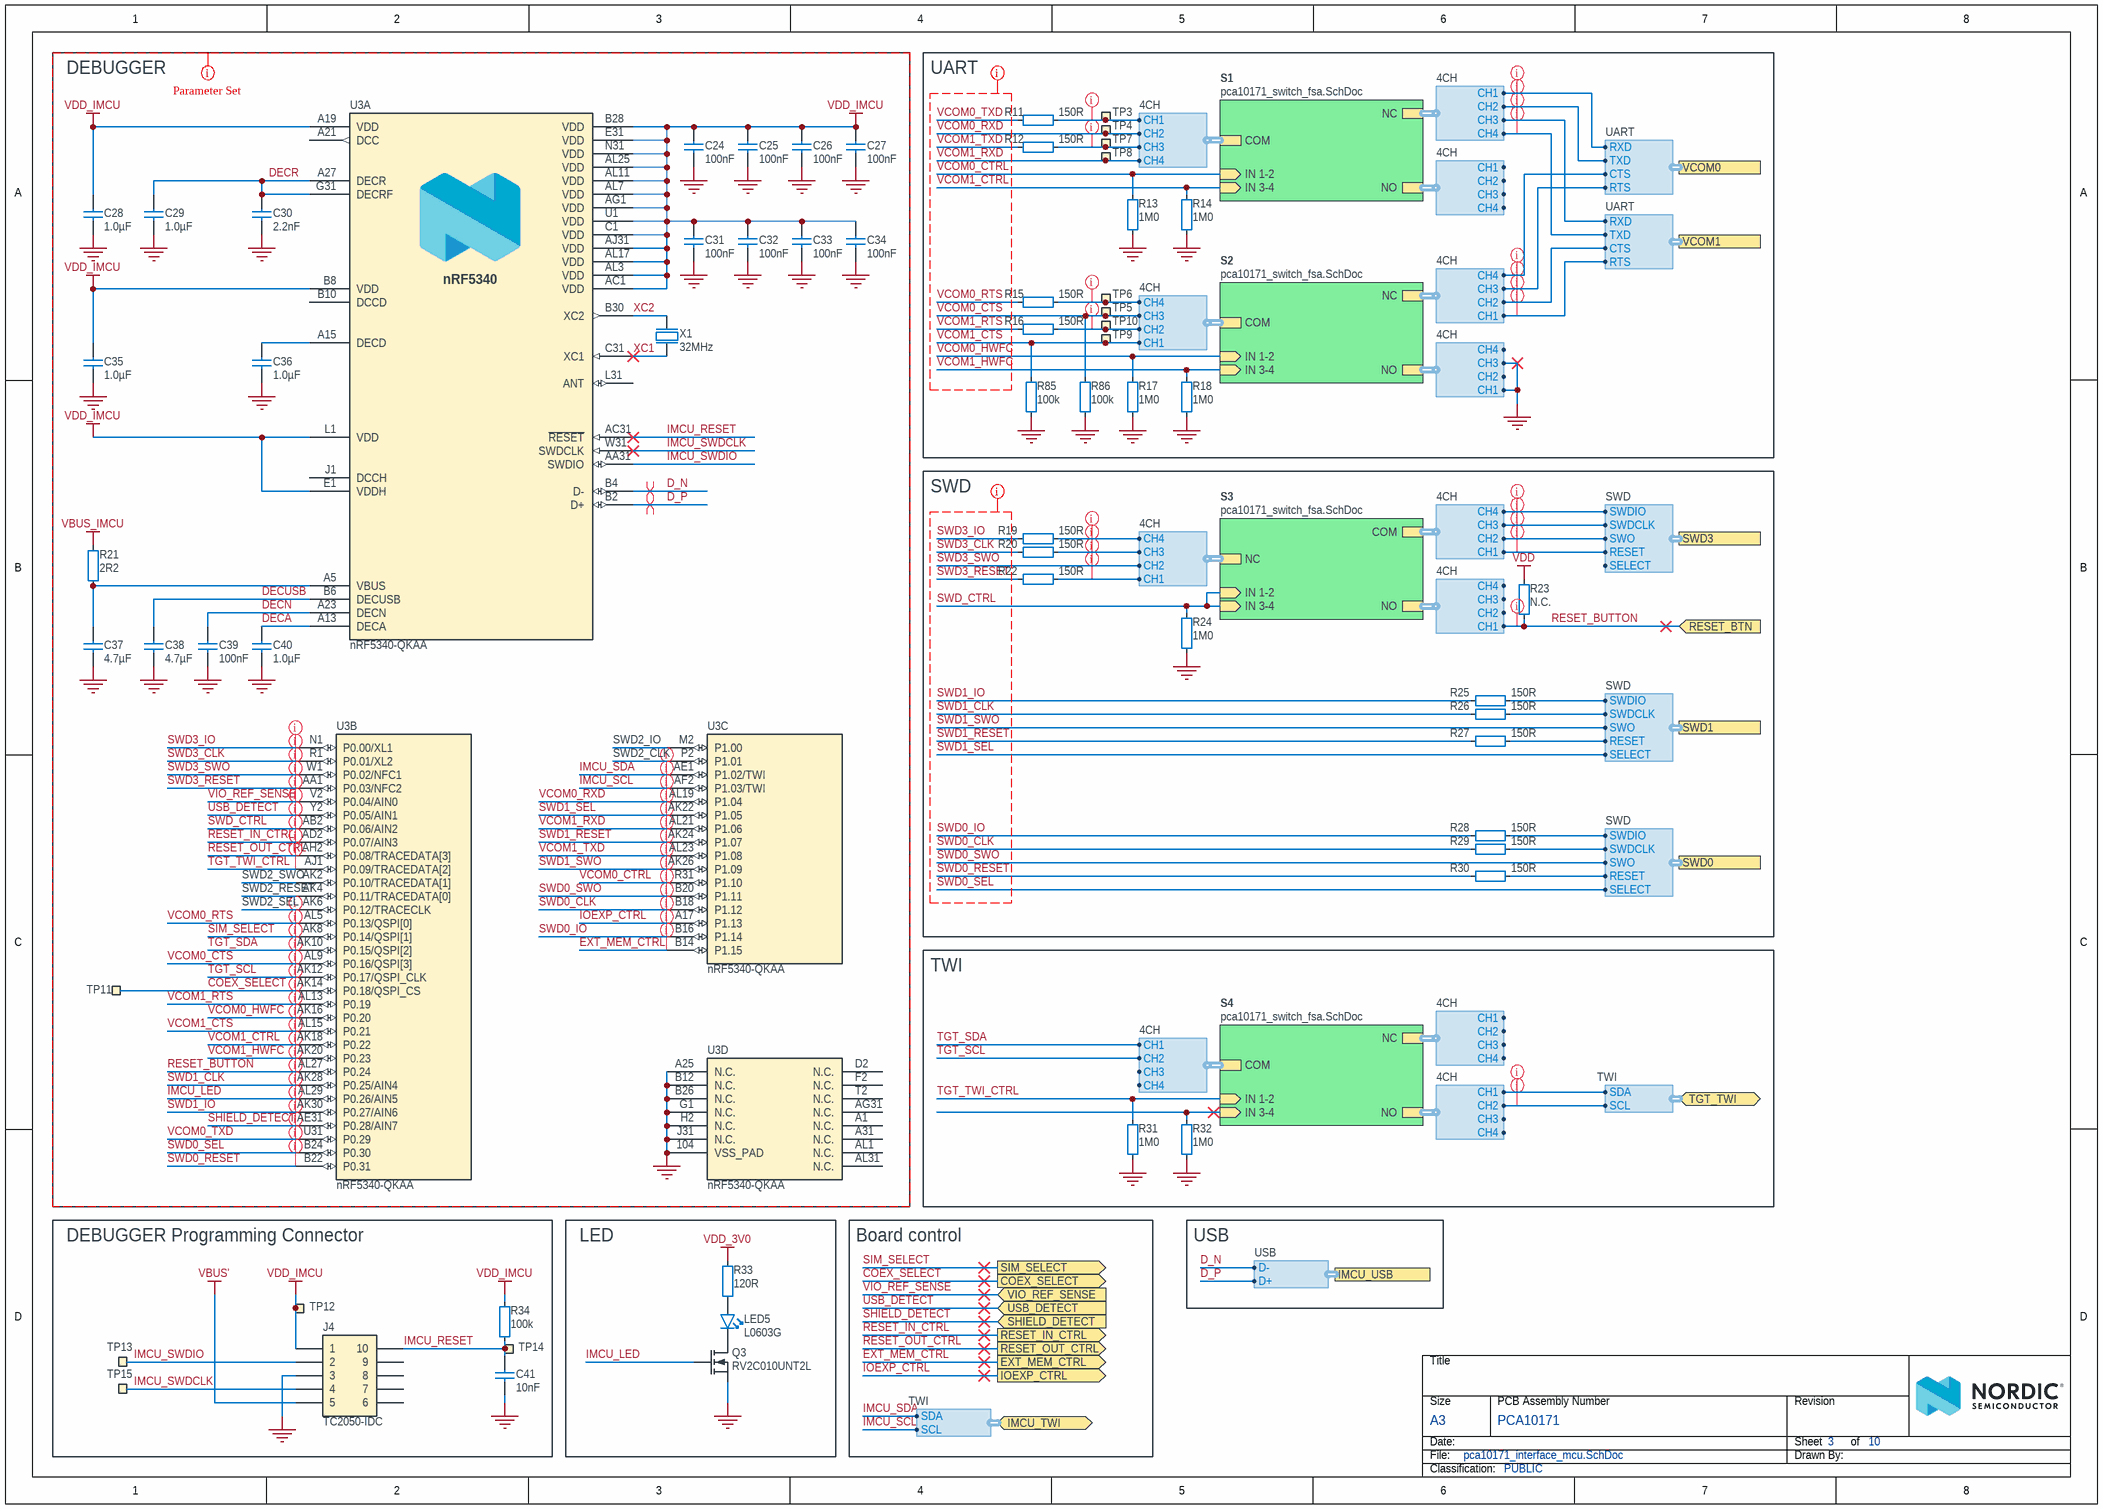
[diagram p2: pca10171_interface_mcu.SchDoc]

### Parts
C24  100nF  [CAPC0603X03L_C]
C25  100nF  [CAPC0603X03L_C]
C26  100nF  [CAPC0603X03L_C]
C27  100nF  [CAPC0603X03L_C]
C28  1.0µF  [CAPC1005X04L]
C29  1.0µF  [CAPC1005X04L]
C30  2.2nF  [CAPC0603X03L_C]
C31  100nF  [CAPC0603X03L_C]
C32  100nF  [CAPC0603X03L_C]
C33  100nF  [CAPC0603X03L_C]
C34  100nF  [CAPC0603X03L_C]
C35  1.0µF  [CAPC1005X04L]
C36  1.0µF  [CAPC1005X04L]
C37  4.7µF  [CAPC1608X06L]
C38  4.7µF  [CAPC1608X06L]
C39  100nF  [CAPC0603X03L_C]
C40  1.0µF  [CAPC1005X04L]
C41  10nF  [CAPC0603X03L_C]
J4  TC2050-IDC  [TC2050-IDC-NLFP]  (no BOM)
LED5  L0603G  [LED_0603_G]
Q3  RV2C010UNT2L  [DFN65P100X40-3L]
R11  150R  [RESC0603X03L_C]
R12  150R  [RESC0603X03L_C]
R13  1M0  [RESC0603X03L_C]
R14  1M0  [RESC0603X03L_C]
R15  150R  [RESC0603X03L_C]
R16  150R  [RESC0603X03L_C]
R17  1M0  [RESC0603X03L_C]
R18  1M0  [RESC0603X03L_C]
R19  150R  [RESC0603X03L_C]
R20  150R  [RESC0603X03L_C]
R21  2R2  [RESC0603X03L_C]
R22  150R  [RESC0603X03L_C]
R23  N.C.  [RESC0603X03L_C_NC]
R24  1M0  [RESC0603X03L_C]
R25  150R  [RESC0603X03L_C]
R26  150R  [RESC0603X03L_C]
R27  150R  [RESC0603X03L_C]
R28  150R  [RESC0603X03L_C]
R29  150R  [RESC0603X03L_C]
R30  150R  [RESC0603X03L_C]
R31  1M0  [RESC0603X03L_C]
R32  1M0  [RESC0603X03L_C]
R33  120R  [RESC0603X03L_C]
R34  100k  [RESC0603X03L_C]
R85  100k  [RESC0603X03L_C]
R86  100k  [RESC0603X03L_C]
TP3  Ø1.5mm,SMD  [TP_SMD_D1.5mm]  (value not drawn)  (no BOM)
TP4  Ø1.5mm,SMD  [TP_SMD_D1.5mm]  (value not drawn)  (no BOM)
TP5  Ø1.5mm,SMD  [TP_SMD_D1.5mm]  (value not drawn)  (no BOM)
TP6  Ø1.5mm,SMD  [TP_SMD_D1.5mm]  (value not drawn)  (no BOM)
TP7  Ø1.5mm,SMD  [TP_SMD_D1.5mm]  (value not drawn)  (no BOM)
TP8  Ø1.5mm,SMD  [TP_SMD_D1.5mm]  (value not drawn)  (no BOM)
TP9  Ø1.5mm,SMD  [TP_SMD_D1.5mm]  (value not drawn)  (no BOM)
TP10  Ø1.5mm,SMD  [TP_SMD_D1.5mm]  (value not drawn)  (no BOM)
TP11  Ø1.5mm,SMD  [TP_SMD_D1.5mm]  (value not drawn)  (no BOM)
TP12  Ø1.5mm,SMD  [TP_SMD_D1.5mm]  (value not drawn)  (no BOM)
TP13  Ø1.5mm,SMD  [TP_SMD_D1.5mm]  (value not drawn)  (no BOM)
TP14  Ø1.5mm,SMD  [TP_SMD_D1.5mm]  (value not drawn)  (no BOM)
TP15  Ø1.5mm,SMD  [TP_SMD_D1.5mm]  (value not drawn)  (no BOM)
U3  nRF5340-QKAA  [AQFN40P700X700X85_HS-99N]  (parts A,B,C,D of 4)
X1  32MHz  [BT-XTAL_2016]

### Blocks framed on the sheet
DEBUGGER: C24-C40 R21 TP11 U3 X1
UART: R11-R18 R85 R86 TP3-TP10
SWD: R19 R20 R22-R30
TWI: R31 R32
DEBUGGER Programming Connector: C41 J4 R34 TP12-TP15
LED: LED5 Q3 R33

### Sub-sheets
S1 = pca10171_switch_fsa.SchDoc: IN 1-2 (in), COM (harness 4CH), NC (harness 4CH), NO (harness 4CH), IN 3-4 (in)
S2 = pca10171_switch_fsa.SchDoc: IN 1-2 (in), COM (harness 4CH), NC (harness 4CH), NO (harness 4CH), IN 3-4 (in)
S3 = pca10171_switch_fsa.SchDoc: IN 1-2 (in), COM (harness 4CH), NC (harness 4CH), NO (harness 4CH), IN 3-4 (in)
S4 = pca10171_switch_fsa.SchDoc: IN 1-2 (in), COM (harness 4CH), NC (harness 4CH), NO (harness 4CH), IN 3-4 (in)

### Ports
COEX_SELECT (out), EXT_MEM_CTRL (out), IMCU_TWI (bidir, harness TWI), IMCU_USB (harness USB), IOEXP_CTRL (out), RESET_BTN (in), RESET_IN_CTRL (out), RESET_OUT_CTRL (out), SHIELD_DETECT (in), SIM_SELECT (out), SWD0 (harness SWD), SWD1 (harness SWD), SWD3 (harness SWD), TGT_TWI (bidir, harness TWI), USB_DETECT (in), VCOM0 (harness UART), VCOM1 (harness UART), VIO_REF_SENSE (in)

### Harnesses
TWI: SCL, SDA
SWD: SWDIO, SWDCLK, SWO, RESET, SELECT
USB: D+, D-
4CH: CH1, CH2, CH3, CH4
UART: RTS, CTS, RXD, TXD

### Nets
GND: C24.1 C25.1 C26.2 C27.1 C28.2 C29.1 C30.2 C31.1 C32.1 C33.1 C34.2 C35.1 C36.1 C37.2 C38.2 C39.2 C40.1 C41.1 J4.3 Q3.2(S) R13.2 R14.1 R17.2 R18.1 R24.1 R31.2 R32.1 R85.2 R86.2 U3.104(VSS_PAD) U3.A25(N.C.) U3.B12(N.C.) U3.B26(N.C.) U3.G1(N.C.) U3.H2(N.C.) U3.J31(N.C.) X1.2(GND) X1.4(GND) ; sheet S2/NO.CH1, sheet S2/NO.CH3
VBUS': J4.5
VBUS_IMCU: R21.1  [project net VBUS]
VDD: R23.2
VDD_3V0: R33.2
VDD_IMCU: C24.2 C25.2 C26.1 C27.2 C28.1 C31.2 C32.2 C33.2 C34.1 C35.2 J4.1 R34.2 TP12.1 U3.A19(VDD) U3.AC1(VDD) U3.AG1(VDD) U3.AJ31(VDD) U3.AL3(VDD) U3.AL7(VDD) U3.AL11(VDD) U3.AL17(VDD) U3.AL25(VDD) U3.B8(VDD) U3.B28(VDD) U3.C1(VDD) U3.E1(VDDH) U3.E31(VDD) U3.L1(VDD) U3.N31(VDD) U3.U1(VDD)
COEX_SELECT: TP11.1 U3.AK14(P0.18/QSPI_CS) ; port COEX_SELECT
D_N: U3.B4(D-) ; port IMCU_USB.D-
D_P: U3.B2(D+) ; port IMCU_USB.D+
DECA: C40.2 U3.A13(DECA)
DECN: C39.1 U3.A23(DECN)
DECR: C29.2 C30.1 U3.A27(DECR) U3.G31(DECRF)
DECUSB: C38.1 U3.B6(DECUSB)
EXT_MEM_CTRL: U3.B14(P1.15) ; port EXT_MEM_CTRL
IMCU_LED: Q3.1(G) U3.AL29(P0.26/AIN5)
IMCU_RESET: C41.2 J4.10 R34.1 TP14.1 U3.AC31(~{RESET})
IMCU_SCL: U3.AF2(P1.03/TWI) ; port IMCU_TWI.SCL
IMCU_SDA: U3.AE1(P1.02/TWI) ; port IMCU_TWI.SDA
IMCU_SWDCLK: J4.4 TP15.1 U3.W31(SWDCLK)
IMCU_SWDIO: J4.2 TP13.1 U3.AA31(SWDIO)
IN 3-4: R32.2 ; sheet S4/IN 3-4
IOEXP_CTRL: U3.A17(P1.13) ; port IOEXP_CTRL
P0.22: sheet S3/COM.CH2, port SWD3.SWO
P0.30: port TGT_TWI.SDA, sheet S4/NO.CH1
P0.31: port TGT_TWI.SCL, sheet S4/NO.CH2
RESET: sheet S3/COM.CH1, port SWD3.RESET
RESET_BUTTON: R23.1 U3.AL27(P0.24) ; port RESET_BTN, sheet S3/NO.CH1
RESET_IN_CTRL: U3.AD2(P0.07/AIN3) ; port RESET_IN_CTRL
RESET_OUT_CTRL: U3.AH2(P0.08/TRACEDATA[3]) ; port RESET_OUT_CTRL
SHIELD_DETECT: U3.AE31(P0.28/AIN7) ; port SHIELD_DETECT
SIM_SELECT: U3.AK8(P0.14/QSPI[1]) ; port SIM_SELECT
SWD0_CLK: R29.1 U3.B18(P1.12)
SWD0_IO: R28.1 U3.B16(P1.14)
SWD0_RESET: R30.1 U3.B22(P0.31)
SWD0_SEL: U3.B24(P0.30) ; port SWD0.SELECT
SWD0_SWO: U3.B20(P1.11) ; port SWD0.SWO
SWD1_CLK: R26.1 U3.AK28(P0.25/AIN4)
SWD1_IO: R25.1 U3.AK30(P0.27/AIN6)
SWD1_RESET: R27.1 U3.AK24(P1.07)
SWD1_SEL: U3.AK22(P1.05) ; port SWD1.SELECT
SWD1_SWO: U3.AK26(P1.09) ; port SWD1.SWO
SWD3_CLK: R20.1 U3.R1(P0.01/XL2)
SWD3_IO: R19.1 U3.N1(P0.00/XL1)
SWD3_RESET: R22.1 U3.AA1(P0.03/NFC2)
SWD3_SWO: U3.W1(P0.02/NFC1) ; sheet S3/NC.CH2
SWD_CTRL: R24.2 U3.AB2(P0.06/AIN2) ; sheet S3/IN 1-2, sheet S3/IN 3-4
SWDCLK: sheet S3/COM.CH3, port SWD3.SWDCLK
SWDIO: sheet S3/COM.CH4, port SWD3.SWDIO
TGT_SCL: U3.AK12(P0.17/QSPI_CLK) ; sheet S4/COM.CH2
TGT_SDA: U3.AK10(P0.15/QSPI[2]) ; sheet S4/COM.CH1
TGT_TWI_CTRL: R31.1 U3.AJ1(P0.09/TRACEDATA[2]) ; sheet S4/IN 1-2
USB_DETECT: U3.Y2(P0.05/AIN1) ; port USB_DETECT
VCOM0_CTRL: R13.1 U3.R31(P1.10) ; sheet S1/IN 1-2
VCOM0_CTS: R86.1 TP5.1 U3.AL9(P0.16/QSPI[3]) ; sheet S2/COM.CH3
VCOM0_HWFC: R17.1 U3.AK16(P0.20) ; sheet S2/IN 1-2
VCOM0_RTS: R15.1 U3.AL5(P0.13/QSPI[0])
VCOM0_RXD: TP4.1 U3.AL19(P1.04) ; sheet S1/COM.CH2
VCOM0_TXD: R11.1 U3.U31(P0.29)
VCOM1_CTRL: R14.2 U3.AK18(P0.22) ; sheet S1/IN 3-4
VCOM1_CTS: R85.1 TP9.1 U3.AL15(P0.21) ; sheet S2/COM.CH1
VCOM1_HWFC: R18.2 U3.AK20(P0.23) ; sheet S2/IN 3-4
VCOM1_RTS: R16.1 U3.AL13(P0.19)
VCOM1_RXD: TP8.1 U3.AL21(P1.06) ; sheet S1/COM.CH4
VCOM1_TXD: R12.1 U3.AL23(P1.08)
VIO_REF_SENSE: U3.V2(P0.04/AIN0) ; port VIO_REF_SENSE
XC1: U3.C31(XC1) X1.1(inp)
XC2: U3.B30(XC2) X1.3(out)
NetC36_2: C36.2 U3.A15(DECD)
NetC37_1: C37.1 R21.2 U3.A5(VBUS)
NetLED5_1: LED5.1(C) Q3.3(D)
NetLED5_2: LED5.2(A) R33.1
NetP19_2: R28.2 ; port SWD0.SWDIO
NetP19_4: R29.2 ; port SWD0.SWDCLK
NetP19_10: R30.2 ; port SWD0.RESET
NetP20_4: R25.2 ; port SWD1.SWDIO
NetP20_5: R26.2 ; port SWD1.SWDCLK
NetP20_7: R27.2 ; port SWD1.RESET
NetP29_2: port VCOM0.RTS, sheet S2/NC.CH3
NetP29_4: sheet S1/NC.CH1, port VCOM0.RXD
NetP29_5: sheet S1/NC.CH2, port VCOM0.TXD
NetP29_6: port VCOM0.CTS, sheet S2/NC.CH4
NetR11_2: R11.2 TP3.1 ; sheet S1/COM.CH1
NetR12_2: R12.2 TP7.1 ; sheet S1/COM.CH3
NetR15_2: R15.2 TP6.1 ; sheet S2/COM.CH4
NetR16_2: R16.2 TP10.1 ; sheet S2/COM.CH2
NetR19_2: R19.2 ; sheet S3/NC.CH4
NetR20_2: R20.2 ; sheet S3/NC.CH3
NetR22_2: R22.2 ; sheet S3/NC.CH1
NetSB7_2: sheet S1/NC.CH3, port VCOM1.RXD
NetSB8_2: sheet S1/NC.CH4, port VCOM1.TXD
NetSB9_2: port VCOM1.RTS, sheet S2/NC.CH1
NetSB10_2: port VCOM1.CTS, sheet S2/NC.CH2

Not connected (* = marked no-connect by the designer): J4 6 7 8 9; U3 A1(N.C.) A21(DCC) A31(N.C.) AG31(N.C.) AK2(P0.10/TRACEDATA[1]) AK4(P0.11/TRACEDATA[0]) AK6(P0.12/TRACECLK) AL1(N.C.) AL31(N.C.) B10(DCCD) D2(N.C.) F2(N.C.) J1(DCCH) L31(ANT) M2(P1.00) P2(P1.01) T2(N.C.)

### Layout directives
differential pair: D_N, D_P
net class GPIO: COEX_SELECT, EXT_MEM_CTRL, IMCU_LED, IMCU_SCL, IMCU_SDA, IOEXP_CTRL, NetP29_2, NetP29_4, NetP29_5, NetP29_6, NetR11_2, NetR12_2, NetR15_2, NetR16_2, NetR19_2, NetR20_2, NetR22_2, NetSB7_2, NetSB8_2, NetSB9_2, NetSB10_2, P0.22, P0.30, P0.31, RESET, RESET_BUTTON, RESET_IN_CTRL, RESET_OUT_CTRL, SHIELD_DETECT, SIM_SELECT, SWD0_CLK, SWD0_IO, SWD0_RESET, SWD0_SEL, SWD0_SWO, SWD1_CLK, SWD1_IO, SWD1_RESET, SWD1_SEL, SWD1_SWO, SWD3_CLK, SWD3_IO, SWD3_RESET, SWD3_SWO, SWD_CTRL, SWDCLK, SWDIO, TGT_SCL, TGT_SDA, TGT_TWI_CTRL, USB_DETECT, VCOM0_CTRL, VCOM0_CTS, VCOM0_HWFC, VCOM0_RTS, VCOM0_RXD, VCOM0_TXD, VCOM1_CTRL, VCOM1_CTS, VCOM1_HWFC, VCOM1_RTS, VCOM1_RXD, VCOM1_TXD, VIO_REF_SENSE
CompClassName: IMCU: COEX_SELECT, D_N, D_P, DECA, DECN, DECR, DECUSB, EXT_MEM_CTRL, GND, IMCU_LED, IMCU_RESET, IMCU_SCL, IMCU_SDA, IMCU_SWDCLK, IMCU_SWDIO, IOEXP_CTRL, RESET_BUTTON, RESET_IN_CTRL, RESET_OUT_CTRL, SHIELD_DETECT, SIM_SELECT, SWD0_CLK, SWD0_IO, SWD0_RESET, SWD0_SEL, SWD0_SWO, SWD1_CLK, SWD1_IO, SWD1_RESET, SWD1_SEL, SWD1_SWO, SWD3_CLK, SWD3_IO, SWD3_RESET, SWD3_SWO, SWD_CTRL, TGT_SCL, TGT_SDA, TGT_TWI_CTRL, USB_DETECT, VBUS_IMCU, VCOM0_CTRL, VCOM0_CTS, VCOM0_HWFC, VCOM0_RTS, VCOM0_RXD, VCOM0_TXD, VCOM1_CTRL, VCOM1_CTS, VCOM1_HWFC, VCOM1_RTS, VCOM1_RXD, VCOM1_TXD, VDD_IMCU, VIO_REF_SENSE, XC1, XC2
net class VCOM: VCOM0_CTRL, VCOM0_CTS, VCOM0_HWFC, VCOM0_RTS, VCOM0_RXD, VCOM0_TXD, VCOM1_CTRL, VCOM1_CTS, VCOM1_HWFC, VCOM1_RTS, VCOM1_RXD, VCOM1_TXD
net class SWD: SWD0_CLK, SWD0_IO, SWD0_RESET, SWD0_SEL, SWD0_SWO, SWD1_CLK, SWD1_IO, SWD1_RESET, SWD1_SEL, SWD1_SWO, SWD3_CLK, SWD3_IO, SWD3_RESET, SWD3_SWO, SWD_CTRL

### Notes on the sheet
- (near U3) SWD2_IO
- (near U3) SWD2_CLK
- (near U3) SWD2_SWO
- (near U3) SWD2_RESET
- (near U3) SWD2_SEL
- Board control
- USB

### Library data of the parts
C24-C27 C31-C33 = C0201-100n: as C4 on sheet pca10171_nrf9151
C28 C29 C35 C36 C40 = C0402-1µ0-10V-X5R: Capacitor, Ceramic, X5R, ±10%, 10V; Manufacturer: N.A.; Part number NEMS: 100200482; Pad Count: 2; Component Status: Active
C30 = C0201-2n2: Capacitor, X7R, ±10%, 10V; Manufacturer: N.A.; Part number IPS: 00000001778; Part number Norautron: 26470002; Part number NEMS: 100200060; Pad Count: 2; Component Status: Active
C34 C39 = C0201-100n: Capacitor, X5R, ±10%; Manufacturer: N.A.; Part number IPS: 00000001248, 00000002505; Part number Norautron: 262071862; Part number NEMS: 100200078; Pad Count: 2; Note: 16V; Component Status: Active
C37 C38 = C0603-4µ7-10V-X5R: Capacitor, Ceramic, X5R, ±10%, 10V; Manufacturer: N.A.; Part number Norautron: 262081761; Part number NEMS: 100200479; Pad Count: 2; Component Status: Active
C41 = C0201-10n: Capacitor, X7R, ±10%; Manufacturer: N.A.; Part number IPS: 00000003480; Part number Norautron: 26621779; Part number NEMS: 100200067; Note: 10V; Pad Count: 2; Component Status: Active
J4 = TC2050-IDC-NLFP: CBL PLUG-OF-NAILS 10-PIN; Manufacturer: Tag-Connect LLC; Part number NEMS: 100500463; Artikkelnr Noca: N.A.; Pad Count: 10; Component Status: Active; System: Connector
LED5 = VS 25C7M5: LED, Green, 0603, 573nm, Vf=2.0V, 24mcd, - 40 to +85°C; Manufacturer: Victory Electronics; Part number IPS: 00000001274, 00000009961; Part number Norautron: 26313411; Part number NEMS: 101400097; Note: N.A.; Artikkelnr Noca: 13019193; Pad Count: 2; Component Status: Active
Q3 = RV2C010UNT2L: as Q2 on sheet pca10171_nrf9151
R11 R12 R15 R16 R19 R20 R22 R25-R30 = R0201-150: Resistor, ±1%, 0.05W; Manufacturer: N.A.; Part number IPS: 00000001420; Part number NEMS: 100100029; Note: Chip Res 1%; Pad Count: 2; Component Status: Active
R13 R14 R17 R18 R24 R31 R32 = R0201-1M0: as R3 on sheet pca10171_nrf9151
R21 = R0201-2R2: Resistor, ±1%, 0.05W; Manufacturer: N.A.; Part number Norautron: 26470029; Part number NEMS: 100100006; Pad Count: 2; Note: Chip Res 1%; Component Status: Active
R23 = R0201-N.C.: as R9 on sheet pca10171_nrf9151
R33 = R0201-120: Resistor, ±1%, 0.05W; Manufacturer: N.A.; Part number IPS: 00000000880; Part number Norautron: 26107076; Part number NEMS: 100100028; Note: Chip Res 1%; Pad Count: 2; Component Status: Active
R34 R85 R86 = R0201-100k: as R10 on sheet pca10171_nrf9151
TP3-TP15 = TP_SMD_Ø1.5MM: 1.5mm circular SMD testpad; Manufacturer: Nordic Semiconductor; Manufacturer Part Number: N.A.; Part number NEMS: 100500477; Pad Count: 1; Component Status: Active
U3 = nRF5340-QKAAD0: Multi-protocol Bluetooth Low Energy, IEEE 802.15.4, ANT and 2.4GHz proprietary system-on-chip; Manufacturer: Nordic Semiconductor; Part number Norautron: NOD26470035; Part number NEMS: 102000216; Pad Count: 98; Note: N.A.; Component Status: Active
X1 = XTAL_SMD2016_32MHz_8pF_Kyocera: XTAL SMD 2016, 32MHz, Cl=8pF, Tot: ±40ppm; Manufacturer Part Number: CX2016DB32000D0WZRC1; Part number IPS: 00000007827; Part number Norautron: 26511136; Part number NEMS: 101600039; Pad Count: 4; Note: XTAL SMD 32.000MHz; Artikkelnr Noca: 22010022; Component Status: Active

## Sheet pca10171_switch_fsa.SchDoc: =BoardTitle + ' - Switch FSA'
size A3; Organization: Nordic Semiconductor; DocumentNumber: 9; Revision: 1.0.0; SheetNumber: 9; SheetTotal: 10; Author: KOD1; CompanyName: Nordic Semiconductor; DrawnBy: KOD1; DocumentSize: A4
Used 9 times, as channels /S1, /S2, /S3, /S4, /S5, /S6, /S8, /S10, /S11. Parts and nets are listed once, with the designators drawn on the sheet.
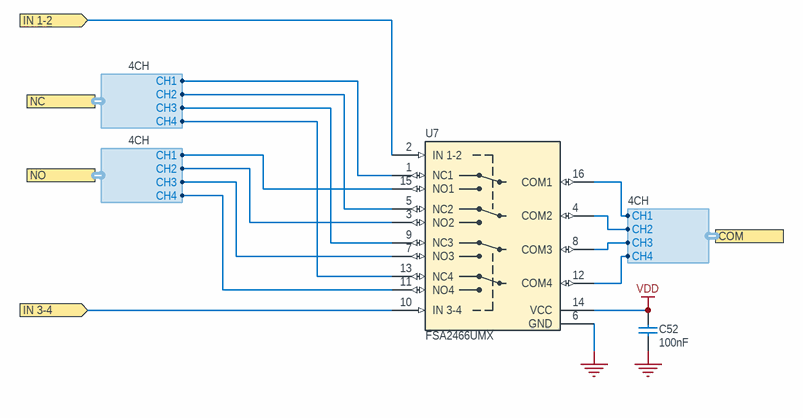
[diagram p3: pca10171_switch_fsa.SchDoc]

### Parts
C52  100nF  [CAPC0603X03L_C]
U7  FSA2466UMX  [XQFN40P180X260X50-16N]

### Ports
COM (harness 4CH), IN 1-2 (in), IN 3-4 (in), NC (harness 4CH), NO (harness 4CH)

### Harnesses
4CH: CH1, CH2, CH3, CH4

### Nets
GND: C52.2 U7.6(GND)
VDD: C52.1 U7.14(VCC)
IN 1-2: U7.2(IN_1-2) ; port IN 1-2
IN 3-4: U7.10(IN_3-4) ; port IN 3-4
NetU7_1: U7.1(NC1) ; port NC.CH1
NetU7_3: U7.3(NO2) ; port NO.CH2
NetU7_4: U7.4(COM2) ; port COM.CH2
NetU7_5: U7.5(NC2) ; port NC.CH2
NetU7_7: U7.7(NO3) ; port NO.CH3
NetU7_8: U7.8(COM3) ; port COM.CH3
NetU7_9: U7.9(NC3) ; port NC.CH3
NetU7_11: U7.11(NO4) ; port NO.CH4
NetU7_12: U7.12(COM4) ; port COM.CH4
NetU7_13: U7.13(NC4) ; port NC.CH4
NetU7_15: U7.15(NO1) ; port NO.CH1
NetU7_16: U7.16(COM1) ; port COM.CH1

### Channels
/S1: designators end in _S1; ports IN 1-2=VCOM0_CTRL IN 3-4=VCOM1_CTRL
/S2: designators end in _S2; ports IN 1-2=VCOM0_HWFC IN 3-4=VCOM1_HWFC
/S3: designators end in _S3; ports IN 1-2=SWD_CTRL IN 3-4=SWD_CTRL
/S4: designators end in _S4; ports IN 1-2=TGT_TWI_CTRL IN 3-4=IN 3-4
/S5: designators end in _S5; ports IN 1-2=IOEXP_CTRL IN 3-4=IOEXP_CTRL
/S6: designators end in _S6; ports IN 1-2=IOEXP_CTRL IN 3-4=IOEXP_CTRL
/S8: designators end in _S8; ports IN 1-2=EXT_MEM_CTRL IN 3-4=EXT_MEM_CTRL
/S10: designators end in _S10; ports IN 1-2=RESET_OUT_CTRL IN 3-4=RESET_IN_CTRL
/S11: designators end in _S11; ports IN 1-2=COEX_SELECT IN 3-4=COEX_SELECT

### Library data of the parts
C52 = C0201-100n: as C4 on sheet pca10171_nrf9151
U7 = FSA2466UMX: Data / Audio Low-Voltage Dual DPDT Analog Switch; Manufacturer: ON Semiconductor; Part number IPS: 00000009986; Part number Norautron: 26500608; Part number NEMS: 101900422; Note: N.A.; Artikkelnr Noca: 15070069; Pad Count: 16; Component Status: Active

## Sheet pca10171_leds_and_buttons.SchDoc: =BoardTitle + ' - LEDs and Buttons'
size A3; Organization: Nordic Semiconductor; DocumentNumber: 4; Revision: 1.0.0; SheetNumber: 4; SheetTotal: 10; Author: KOD1; CompanyName: Nordic Semiconductor; DrawnBy: KOD1; DocumentSize: A3
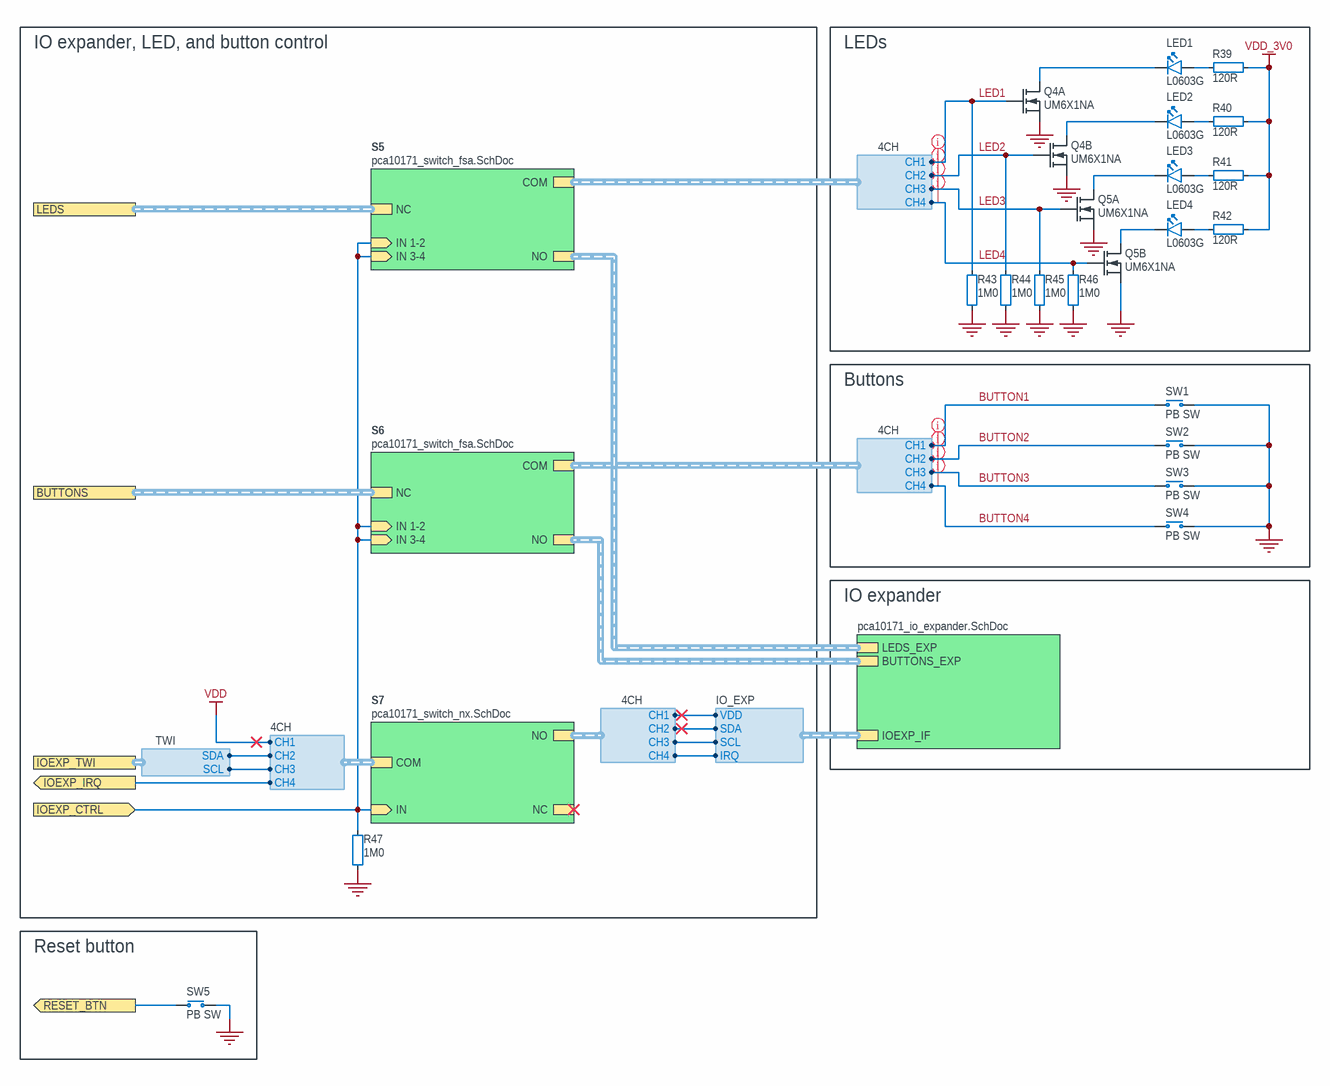
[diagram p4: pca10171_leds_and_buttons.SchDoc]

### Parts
LED1  L0603G  [LED_0603_G]
LED2  L0603G  [LED_0603_G]
LED3  L0603G  [LED_0603_G]
LED4  L0603G  [LED_0603_G]
Q4  UM6X1NA  [SOTFL50P162X60-6N]  (parts A,B of 2)
Q5  UM6X1NA  [SOTFL50P162X60-6N]  (parts A,B of 2)
R39  120R  [RESC0603X03L_C]
R40  120R  [RESC0603X03L_C]
R41  120R  [RESC0603X03L_C]
R42  120R  [RESC0603X03L_C]
R43  1M0  [RESC0603X03L_C]
R44  1M0  [RESC0603X03L_C]
R45  1M0  [RESC0603X03L_C]
R46  1M0  [RESC0603X03L_C]
R47  1M0  [RESC0603X03L_C]
SW1  PB SW  [L-KLS7-TS6616B-2.5-160-T]
SW2  PB SW  [L-KLS7-TS6616B-2.5-160-T]
SW3  PB SW  [L-KLS7-TS6616B-2.5-160-T]
SW4  PB SW  [L-KLS7-TS6616B-2.5-160-T]
SW5  PB SW  [L-KLS7-TS6616B-2.5-160-T]

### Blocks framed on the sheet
IO expander, LED, and button control: R47
LEDs: LED1-LED4 Q4 Q5 R39-R46
Buttons: SW1-SW4
Reset button: SW5

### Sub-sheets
Designator = pca10171_io_expander.SchDoc: LEDS_EXP (harness 4CH), BUTTONS_EXP (harness 4CH), IOEXP_IF (harness IO_EXP)
S5 = pca10171_switch_fsa.SchDoc: IN 1-2 (in), COM (harness 4CH), NC (harness 4CH), NO (harness 4CH), IN 3-4 (in)
S6 = pca10171_switch_fsa.SchDoc: IN 1-2 (in), COM (harness 4CH), NC (harness 4CH), NO (harness 4CH), IN 3-4 (in)
S7 = pca10171_switch_nx.SchDoc: IN (in), COM (harness 4CH), NC (harness 4CH), NO (harness 4CH)

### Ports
BUTTONS (harness 4CH), IOEXP_CTRL (in), IOEXP_IRQ (out), IOEXP_TWI (harness TWI), LEDS (harness 4CH), RESET_BTN (out)

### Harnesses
4CH: CH1, CH2, CH3, CH4
IO_EXP: VDD, SCL, SDA, IRQ
TWI: SCL, SDA

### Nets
GND: Q4.1(S1) Q4.4(S2) Q5.1(S1) Q5.4(S2) R43.1 R44.1 R45.1 R46.1 R47.1 SW1.1(N.O) SW2.1(N.O) SW3.1(N.O) SW4.1(N.O) SW5.1(N.O)
VDD_3V0: R39.2 R40.2 R41.2 R42.2
VIOEXT: sheet S7/NO.CH1, sheet Designator/IOEXP_IF.VDD
BUTTON1: SW1.2(COM) ; sheet S6/COM.CH1
BUTTON2: SW2.2(COM) ; sheet S6/COM.CH2
BUTTON3: SW3.2(COM) ; sheet S6/COM.CH3
BUTTON4: SW4.2(COM) ; sheet S6/COM.CH4
INT_EXT: sheet S7/NO.CH4, sheet Designator/IOEXP_IF.IRQ
IOEXP_CTRL: R47.2 ; port IOEXP_CTRL, sheet S5/IN 1-2, sheet S5/IN 3-4, sheet S6/IN 1-2, sheet S6/IN 3-4, sheet S7/IN
LED1: Q4.2(G1) R43.2 ; sheet S5/COM.CH1
LED2: Q4.5(G2) R44.2 ; sheet S5/COM.CH2
LED3: Q5.2(G1) R45.2 ; sheet S5/COM.CH3
LED4: Q5.5(G2) R46.2 ; sheet S5/COM.CH4
P0.19/AIN6: port IOEXP_IRQ, sheet S7/COM.CH4
P0.30: sheet S7/COM.CH2, port IOEXP_TWI.SDA
P0.31: sheet S7/COM.CH3, port IOEXP_TWI.SCL
RESET_BUTTON: SW5.2(COM) ; port RESET_BTN
SCL_EXT: sheet S7/NO.CH3, sheet Designator/IOEXP_IF.SCL
SDA_EXT: sheet S7/NO.CH2, sheet Designator/IOEXP_IF.SDA
NetLED1_1: LED1.1(C) Q4.6(D1)
NetLED1_2: LED1.2(A) R39.1
NetLED2_1: LED2.1(C) Q4.3(D2)
NetLED2_2: LED2.2(A) R40.1
NetLED3_1: LED3.1(C) Q5.6(D1)
NetLED3_2: LED3.2(A) R41.1
NetLED4_1: LED4.1(C) Q5.3(D2)
NetLED4_2: LED4.2(A) R42.1

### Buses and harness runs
harness port BUTTONS = sheet S6/NC
harness port LEDS = sheet S5/NC
harness sheet Designator/BUTTONS_EXP = sheet S6/NO
harness sheet Designator/LEDS_EXP = sheet S5/NO

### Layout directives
net class GPIO: BUTTON1, BUTTON2, BUTTON3, BUTTON4, LED1, LED2, LED3, LED4

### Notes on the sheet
- IO expander

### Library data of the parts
LED1-LED4 = VS 25C7M5: as LED5 on sheet pca10171_interface_mcu
Q4 Q5 = UM6X1NA: Dual N-Channel MOSFET, Vds = 30V, Vgs(th) = 1.5V, Id = 0.5A, Rds = 750mOhm, Pd = 150mW; Manufacturer: Micro Commercial Components; Manufacturer Part Number: UM6X1NA-TP; Part number NEMS: 101300201; Note: N.A.; Pad Count: 6; Component Status: Active
R39-R42 = R0201-120: as R33 on sheet pca10171_interface_mcu
R43-R47 = R0201-1M0: as R3 on sheet pca10171_nrf9151
SW1-SW5 = L-KLS7-TS6616B-2.5-160-T: Tactile Switch, SPNO, SMD, 160gf, 6.2x6.4x2.5mm; Manufacturer: KLS; Part number NEMS: 101500133, 101500001; Note: N.A.; Pad Count: 4; Component Status: Active

## Sheet pca10171_switch_nx.SchDoc: =BoardTitle + ' - Switch NX'
size A3; Organization: Nordic Semiconductor; DocumentNumber: 10; Revision: 1.0.0; SheetNumber: 10; SheetTotal: 10; Author: KOD1; CompanyName: Nordic Semiconductor; DrawnBy: KOD1; DocumentSize: A4
Used 2 times, as channels /S7, /S9. Parts and nets are listed once, with the designators drawn on the sheet.
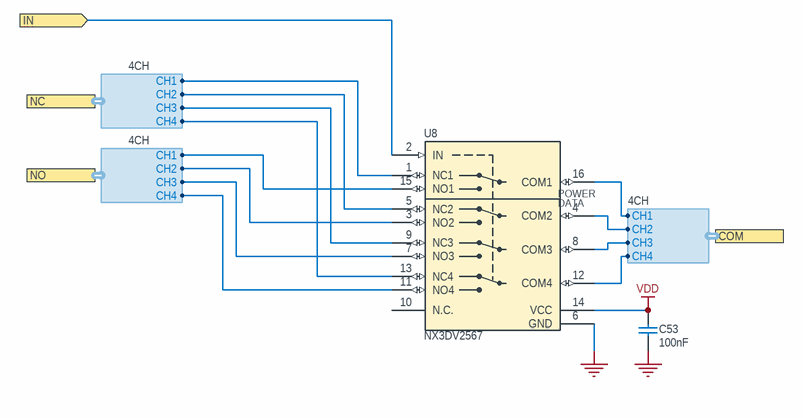
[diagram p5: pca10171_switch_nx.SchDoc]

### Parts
C53  100nF  [CAPC0603X03L_C]
U8  NX3DV2567  [XQFN40P180X260X50-16N]

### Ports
COM (harness 4CH), IN (in), NC (harness 4CH), NO (harness 4CH)

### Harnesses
4CH: CH1, CH2, CH3, CH4

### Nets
GND: C53.2 U8.6(GND)
VDD: C53.1 U8.14(VCC)
IN: U8.2(IN) ; port IN
NetU8_1: U8.1(NC1) ; port NC.CH1
NetU8_3: U8.3(NO2) ; port NO.CH2
NetU8_4: U8.4(COM2) ; port COM.CH2
NetU8_5: U8.5(NC2) ; port NC.CH2
NetU8_7: U8.7(NO3) ; port NO.CH3
NetU8_8: U8.8(COM3) ; port COM.CH3
NetU8_9: U8.9(NC3) ; port NC.CH3
NetU8_11: U8.11(NO4) ; port NO.CH4
NetU8_12: U8.12(COM4) ; port COM.CH4
NetU8_13: U8.13(NC4) ; port NC.CH4
NetU8_15: U8.15(NO1) ; port NO.CH1
NetU8_16: U8.16(COM1) ; port COM.CH1

Not connected (* = marked no-connect by the designer): U8 10(N.C.)

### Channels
/S7: designators end in _S7; ports IN=IOEXP_CTRL
/S9: designators end in _S9; ports IN=SIM_SELECT

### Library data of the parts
C53 = C0201-100n: as C4 on sheet pca10171_nrf9151
U8 = NX3DV2567GU: Low-ohmic four-pole double-throw analog switch; Manufacturer: NXP Semiconductors; Part number IPS: 00000007816; Part number NEMS: 101900290; Note: N.A.; Artikkelnr Noca: 15079317; Pad Count: 16; Component Status: Active

## Sheet pca10171_io_expander.SchDoc: =BoardTitle + ' - IO Expander'
size A3; Organization: Nordic Semiconductor; DocumentNumber: 5; Revision: 1.0.0; SheetNumber: 5; SheetTotal: 10; Author: KOD1; CompanyName: Nordic Semiconductor; DrawnBy: KOD1; DocumentSize: A3
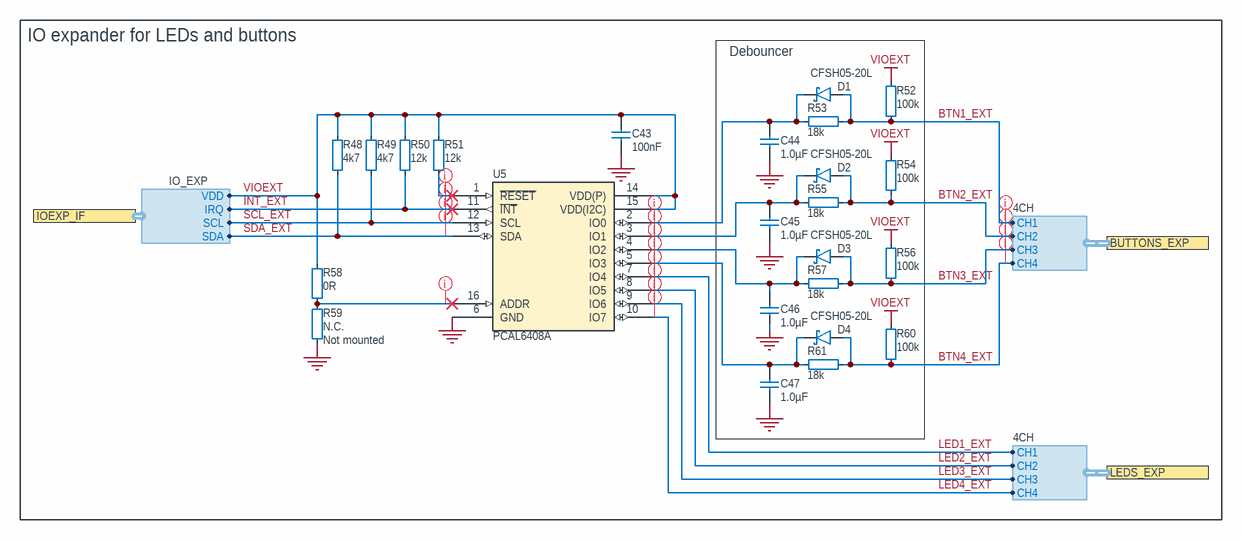
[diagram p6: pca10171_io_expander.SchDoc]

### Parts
C43  100nF  [CAPC0603X03L_C]
C44  1.0µF  [CAPC0603X03L_C]
C45  1.0µF  [CAPC0603X03L_C]
C46  1.0µF  [CAPC0603X03L_C]
C47  1.0µF  [CAPC0603X03L_C]
D1  CFSH05-20L  [SODFL35X40-2N]
D2  CFSH05-20L  [SODFL35X40-2N]
D3  CFSH05-20L  [SODFL35X40-2N]
D4  CFSH05-20L  [SODFL35X40-2N]
R48  4k7  [RESC0603X03L_C]
R49  4k7  [RESC0603X03L_C]
R50  12k  [RESC0603X03L_C]
R51  12k  [RESC0603X03L_C]
R52  100k  [RESC0603X03L_C]
R53  18k  [RESC0603X03L_C]
R54  100k  [RESC0603X03L_C]
R55  18k  [RESC0603X03L_C]
R56  100k  [RESC0603X03L_C]
R57  18k  [RESC0603X03L_C]
R58  0R  [RESC0603X03L_C]
R59  N.C.  Assembly: Not mounted  [RESC0603X03L_C_NC]
R60  100k  [RESC0603X03L_C]
R61  18k  [RESC0603X03L_C]
U5  PCAL6408A  [XQFN40P180X260X50-16N]

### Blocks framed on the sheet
IO expander for LEDs and buttons: C43 R48-R51 R58 R59 U5
Debouncer: C44-C47 D1-D4 R52-R57 R60 R61

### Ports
BUTTONS_EXP (harness 4CH), IOEXP_IF (harness IO_EXP), LEDS_EXP (harness 4CH)

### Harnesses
IO_EXP: VDD, SCL, SDA, IRQ
4CH: CH1, CH2, CH3, CH4

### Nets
GND: C43.1 C44.2 C45.1 C46.1 C47.1 R59.1 U5.6(GND)
VIOEXT: C43.2 R48.2 R49.2 R50.2 R51.2 R52.2 R54.2 R56.2 R58.2 R60.2 U5.14(VDD(P)) U5.15(VDD(I2C)) ; port IOEXP_IF.VDD
BTN1_EXT: D1.1(A) R52.1 R53.2 ; port BUTTONS_EXP.CH1
BTN2_EXT: D2.1(A) R54.1 R55.2 ; port BUTTONS_EXP.CH2
BTN3_EXT: D3.1(A) R56.1 R57.2 ; port BUTTONS_EXP.CH3
BTN4_EXT: D4.1(A) R60.1 R61.2 ; port BUTTONS_EXP.CH4
INT_EXT: R50.1 U5.11(~{INT}) ; port IOEXP_IF.IRQ
LED1_EXT: U5.7(IO4) ; port LEDS_EXP.CH1
LED2_EXT: U5.8(IO5) ; port LEDS_EXP.CH2
LED3_EXT: U5.9(IO6) ; port LEDS_EXP.CH3
LED4_EXT: U5.10(IO7) ; port LEDS_EXP.CH4
SCL_EXT: R49.1 U5.12(SCL) ; port IOEXP_IF.SCL
SDA_EXT: R48.1 U5.13(SDA) ; port IOEXP_IF.SDA
NetC44_1: C44.1 D1.3(C) R53.1 U5.2(IO0)
NetC45_2: C45.2 D2.3(C) R55.1 U5.3(IO1)
NetC46_2: C46.2 D3.3(C) R57.1 U5.4(IO2)
NetC47_2: C47.2 D4.3(C) R61.1 U5.5(IO3)
NetR51_1: R51.1 U5.1(~{RESET})
NetR58_1: R58.1 R59.2 U5.16(ADDR)

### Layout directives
net class GPIO: BTN1_EXT, BTN2_EXT, BTN3_EXT, BTN4_EXT, INT_EXT, LED1_EXT, LED2_EXT, LED3_EXT, LED4_EXT, NetC44_1, NetC45_2, NetC46_2, NetC47_2, NetR51_1, NetR58_1, SCL_EXT, SDA_EXT

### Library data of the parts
C43 = C0201-100n: as C4 on sheet pca10171_nrf9151
C44-C47 = C0201-1µ0: Capacitor, X5R, ±10%; Manufacturer: N.A.; Part number IPS: 00000001723; Part number NEMS: 100200084; Note: 10V; Pad Count: 2; Component Status: Active
D1-D4 = CFSH05-20L: DIODE SCHOTTKY 20V 500MA SOD882; Manufacturer: Central Semiconductor Corp.; Part number IPS: 00000002493; Part number NEMS: 101300101; Note: N.A.; Pad Count: 2; Component Status: Active
R48 R49 = R0201-4k7: Resistor, ±1%, 0.05W; Manufacturer: N.A.; Part number IPS: 00000001706; Part number NEMS: 100100061; Note: Chip Res 1%; Pad Count: 2; Component Status: Active
R50 R51 = R0201-12k: Resistor, ±1%, 0.05W; Manufacturer: N.A.; Part number IPS: 00000007891; Part number Norautron: 26192279; Part number NEMS: 100100066; Note: Chip Res 1%; Pad Count: 2; Component Status: Active
R52 R54 R56 R60 = R0201-100k: as R10 on sheet pca10171_nrf9151
R53 R55 R57 R61 = R0201-18k: Resistor, ±1%, 0.05W; Manufacturer: N.A.; Part number IPS: 00000001707; Part number NEMS: 100100069; Note: Chip Res 1%; Pad Count: 2; Component Status: Active
R58 = R0201-0R: Resistor, ±5%, 0.05W; Manufacturer: N.A.; Part number IPS: 00000003245; Part number NEMS: 100100001; Note: Chip Res 5%; Pad Count: 2; Component Status: Active
R59 = R0201-N.C.: Not mounted; Manufacturer: N.A.; Part number NEMS: 100100107; Note: Chip Res; Pad Count: 2; Component Status: Active
U5 = PCAL6408AHK: 8-bit I2C-bus I/O expander with interrupt output; Manufacturer: NXP Semiconductors; Part number IPS: 00000009987; Part number NEMS: 101900289; Note: N.A.; Artikkelnr Noca: 15079321; Pad Count: 16; Component Status: Active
